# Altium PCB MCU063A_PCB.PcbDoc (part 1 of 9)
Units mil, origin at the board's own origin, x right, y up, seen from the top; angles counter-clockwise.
Board outline 4165.01 x 2371.03 mil, 10 copper layers (Top Layer, Internal Plane 2, Signal Layer 3, Signal Layer 4, Internal Plane 5, Internal Plane 6, Signal Layer 7, Signal Layer 8, Internal Plane 9, Bottom), stack 59.9 mil thick; 436 components, 392 nets, 1750 pads, 1250 vias.
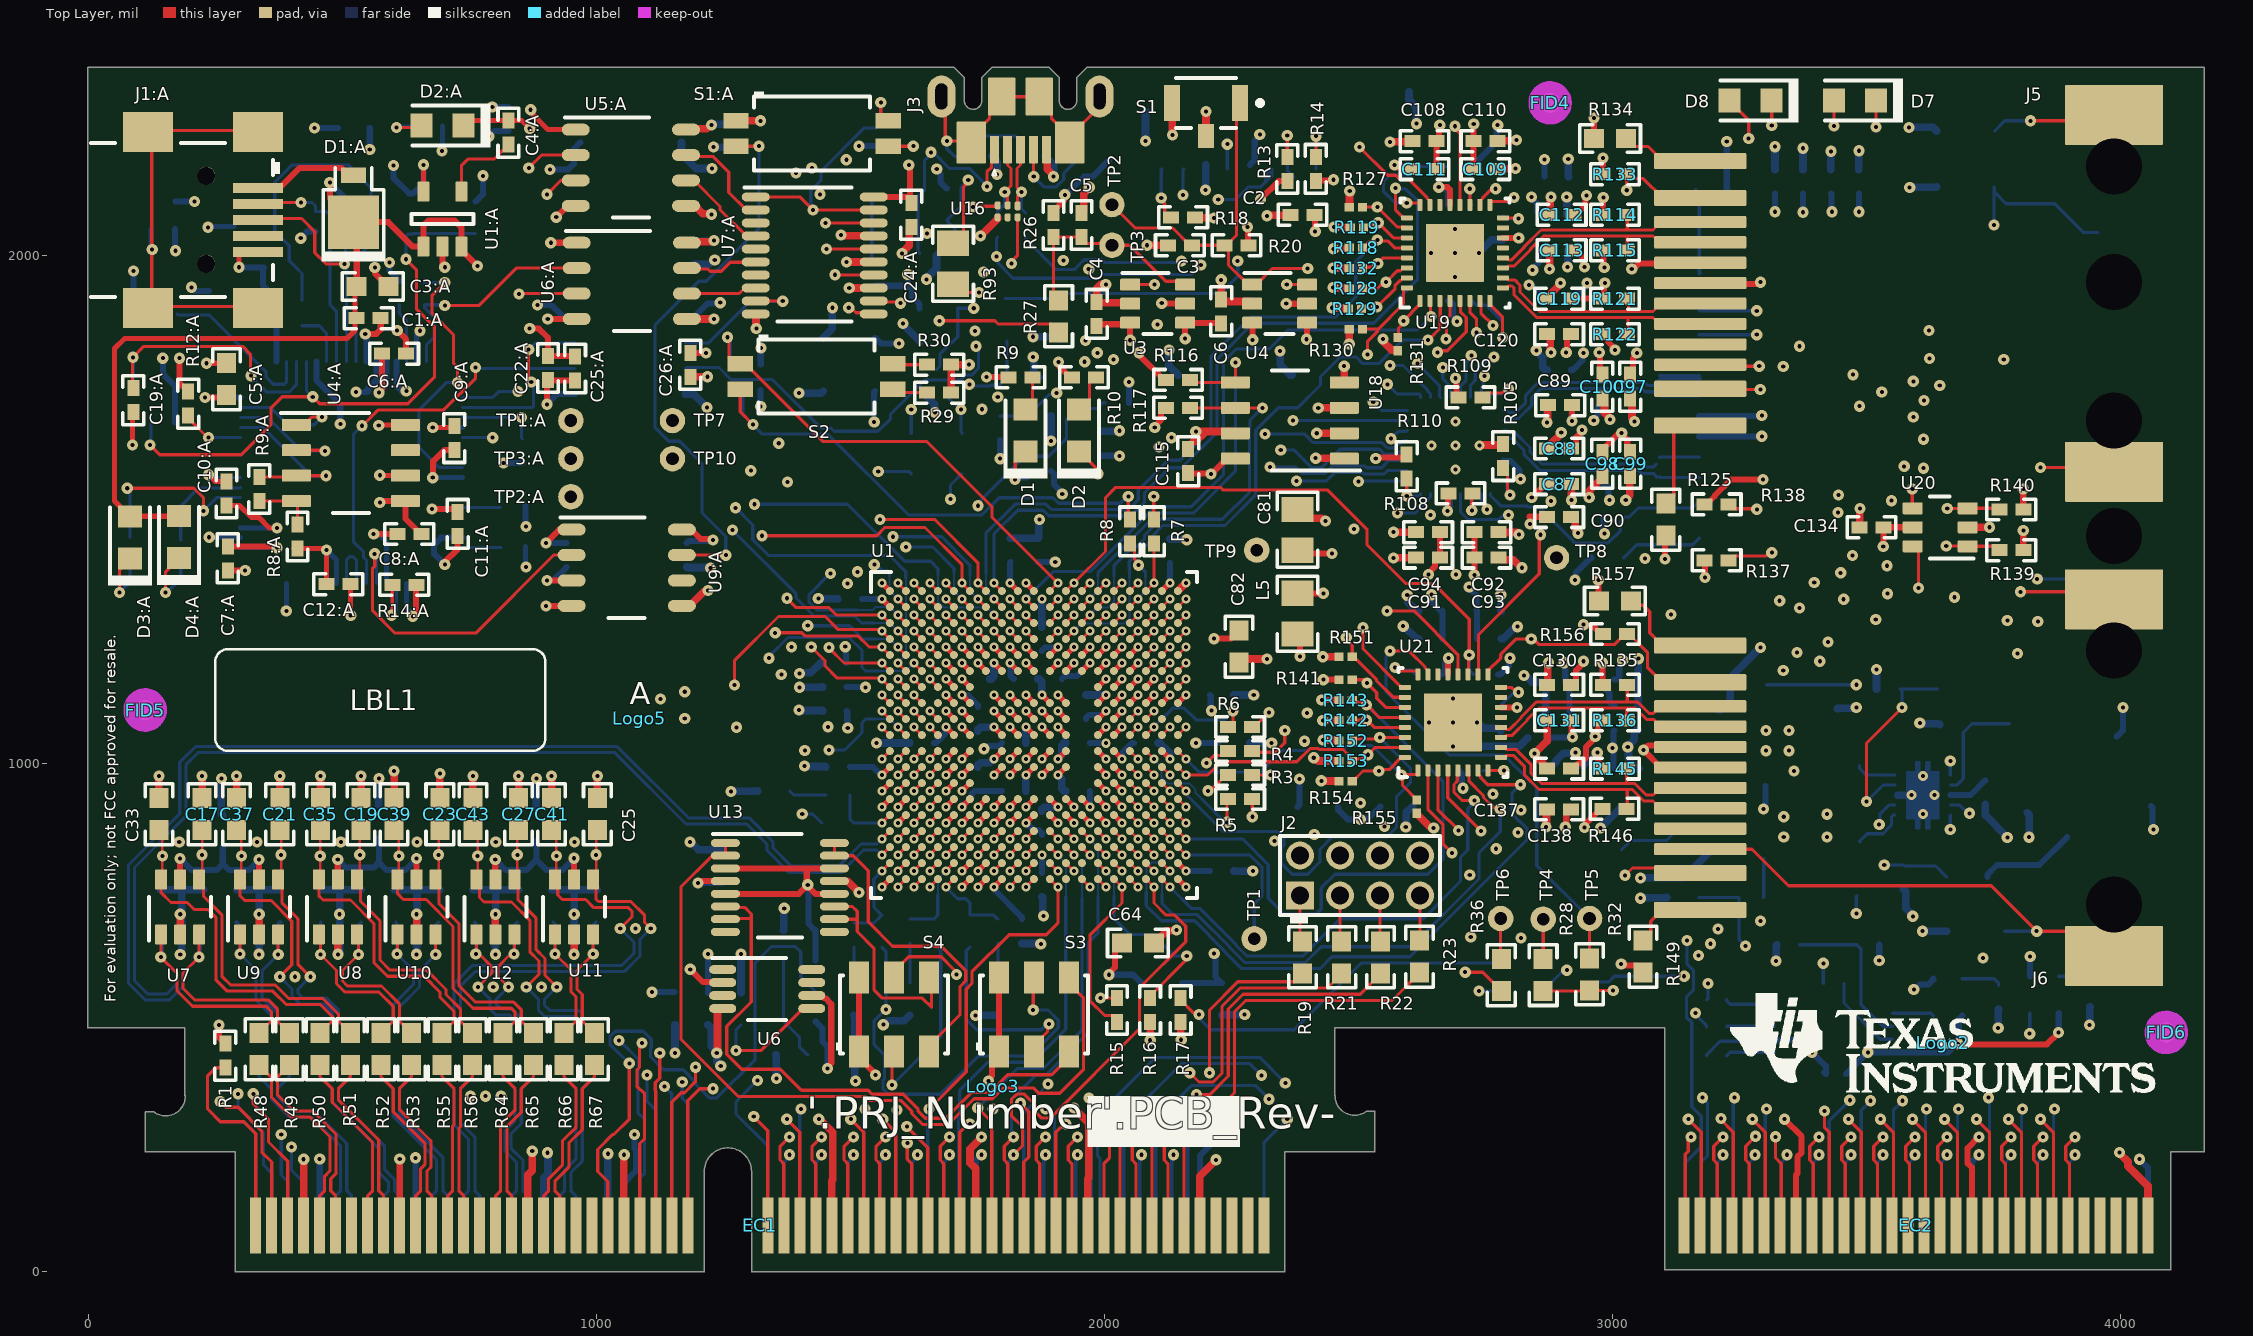
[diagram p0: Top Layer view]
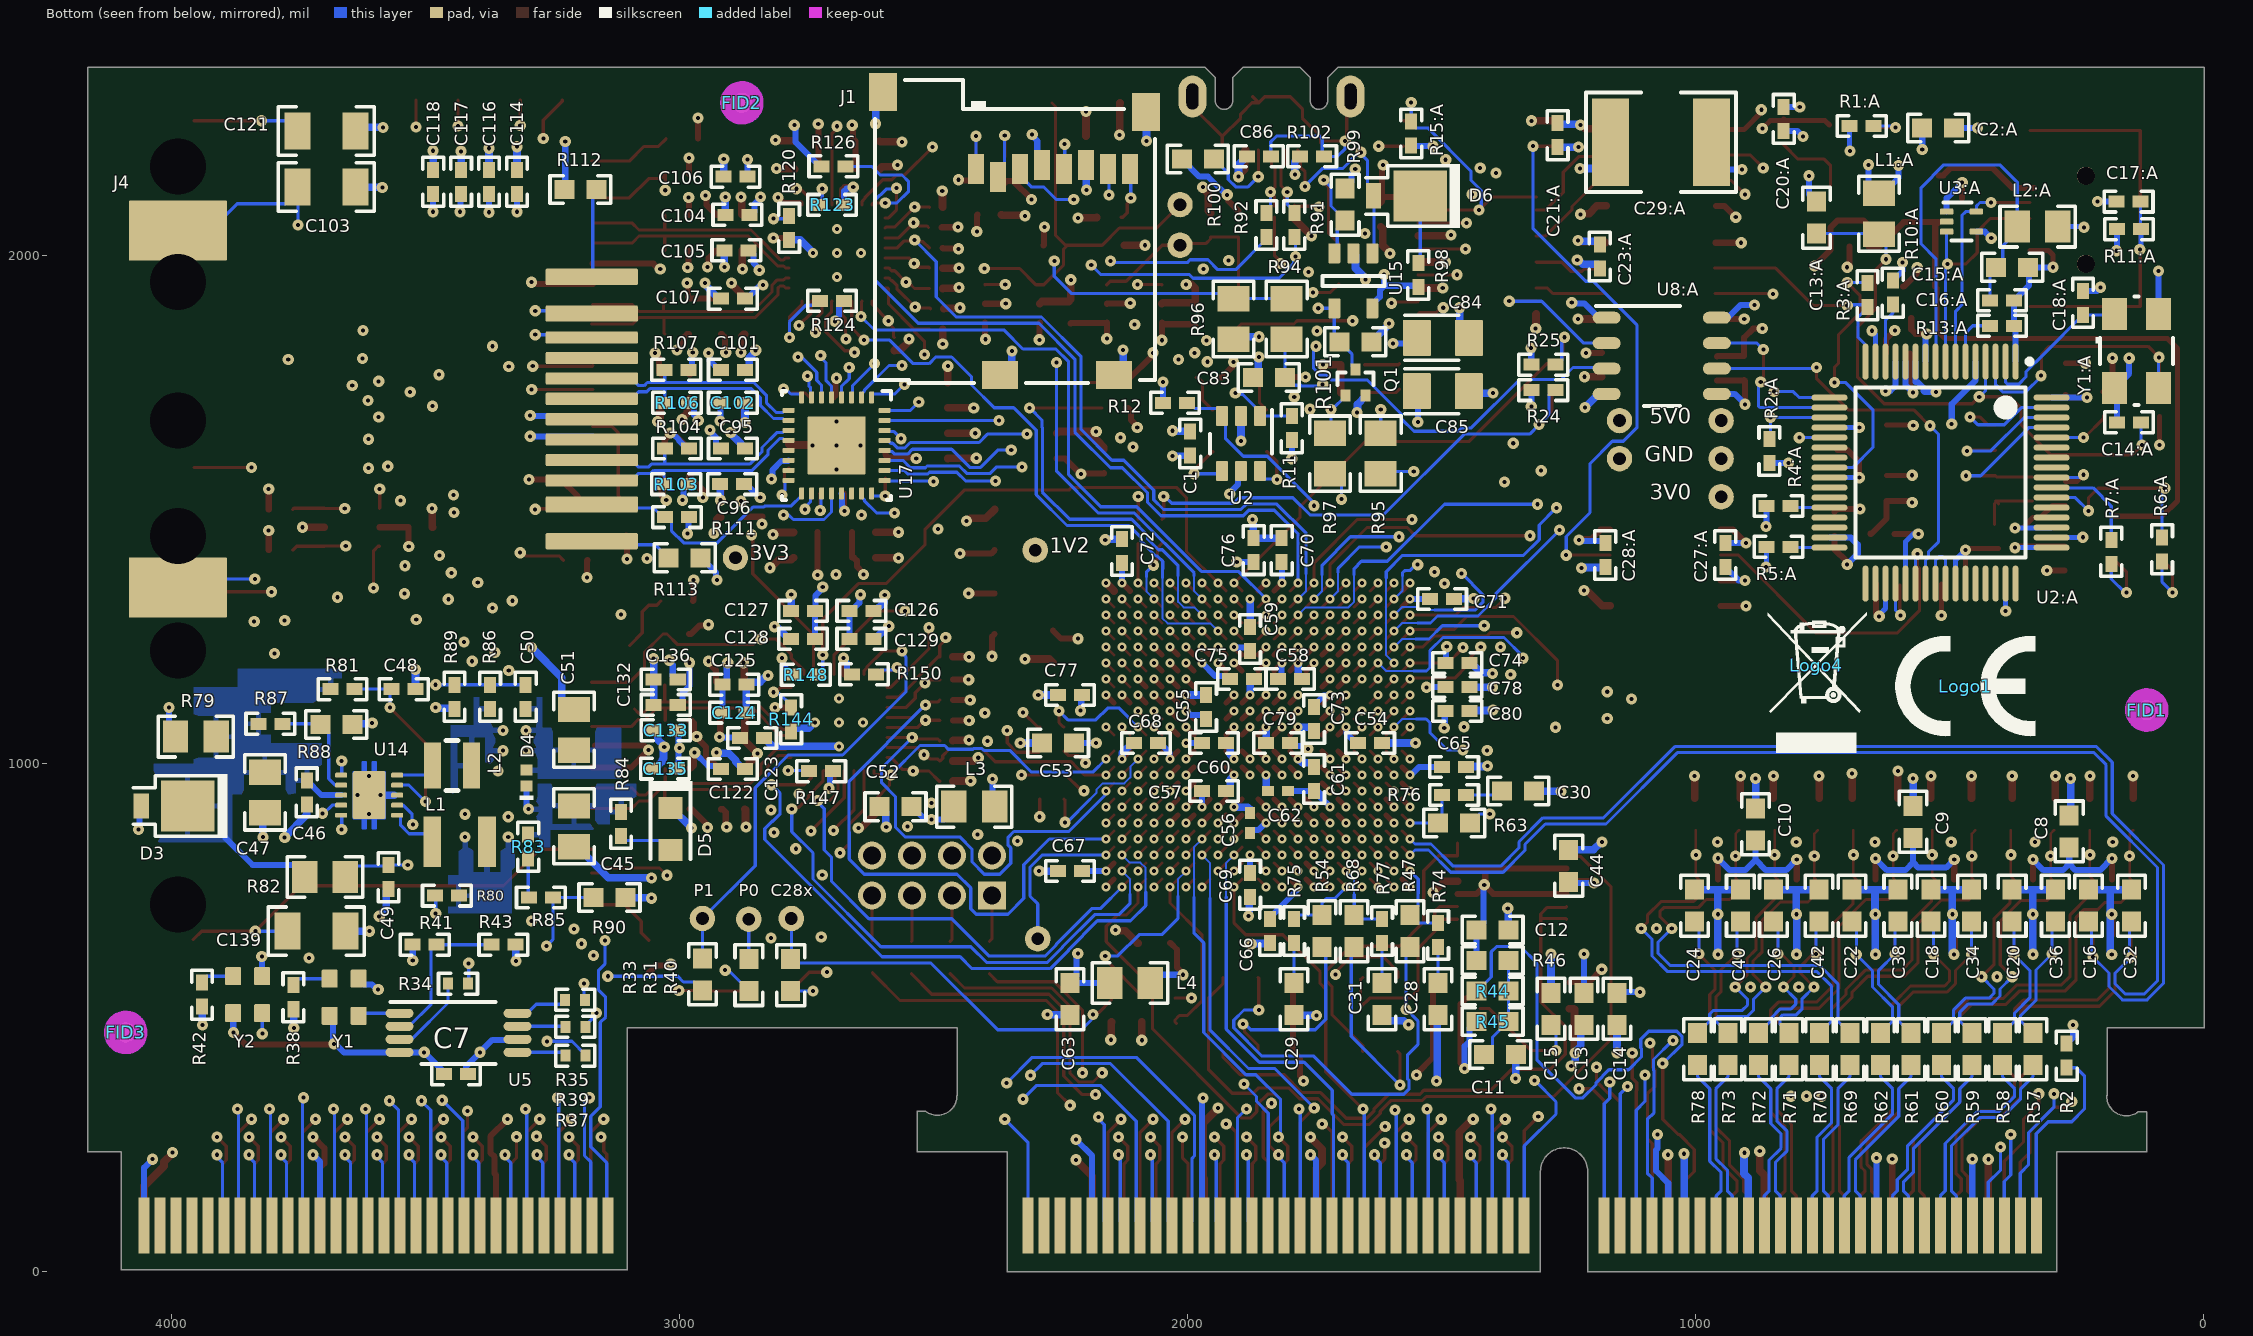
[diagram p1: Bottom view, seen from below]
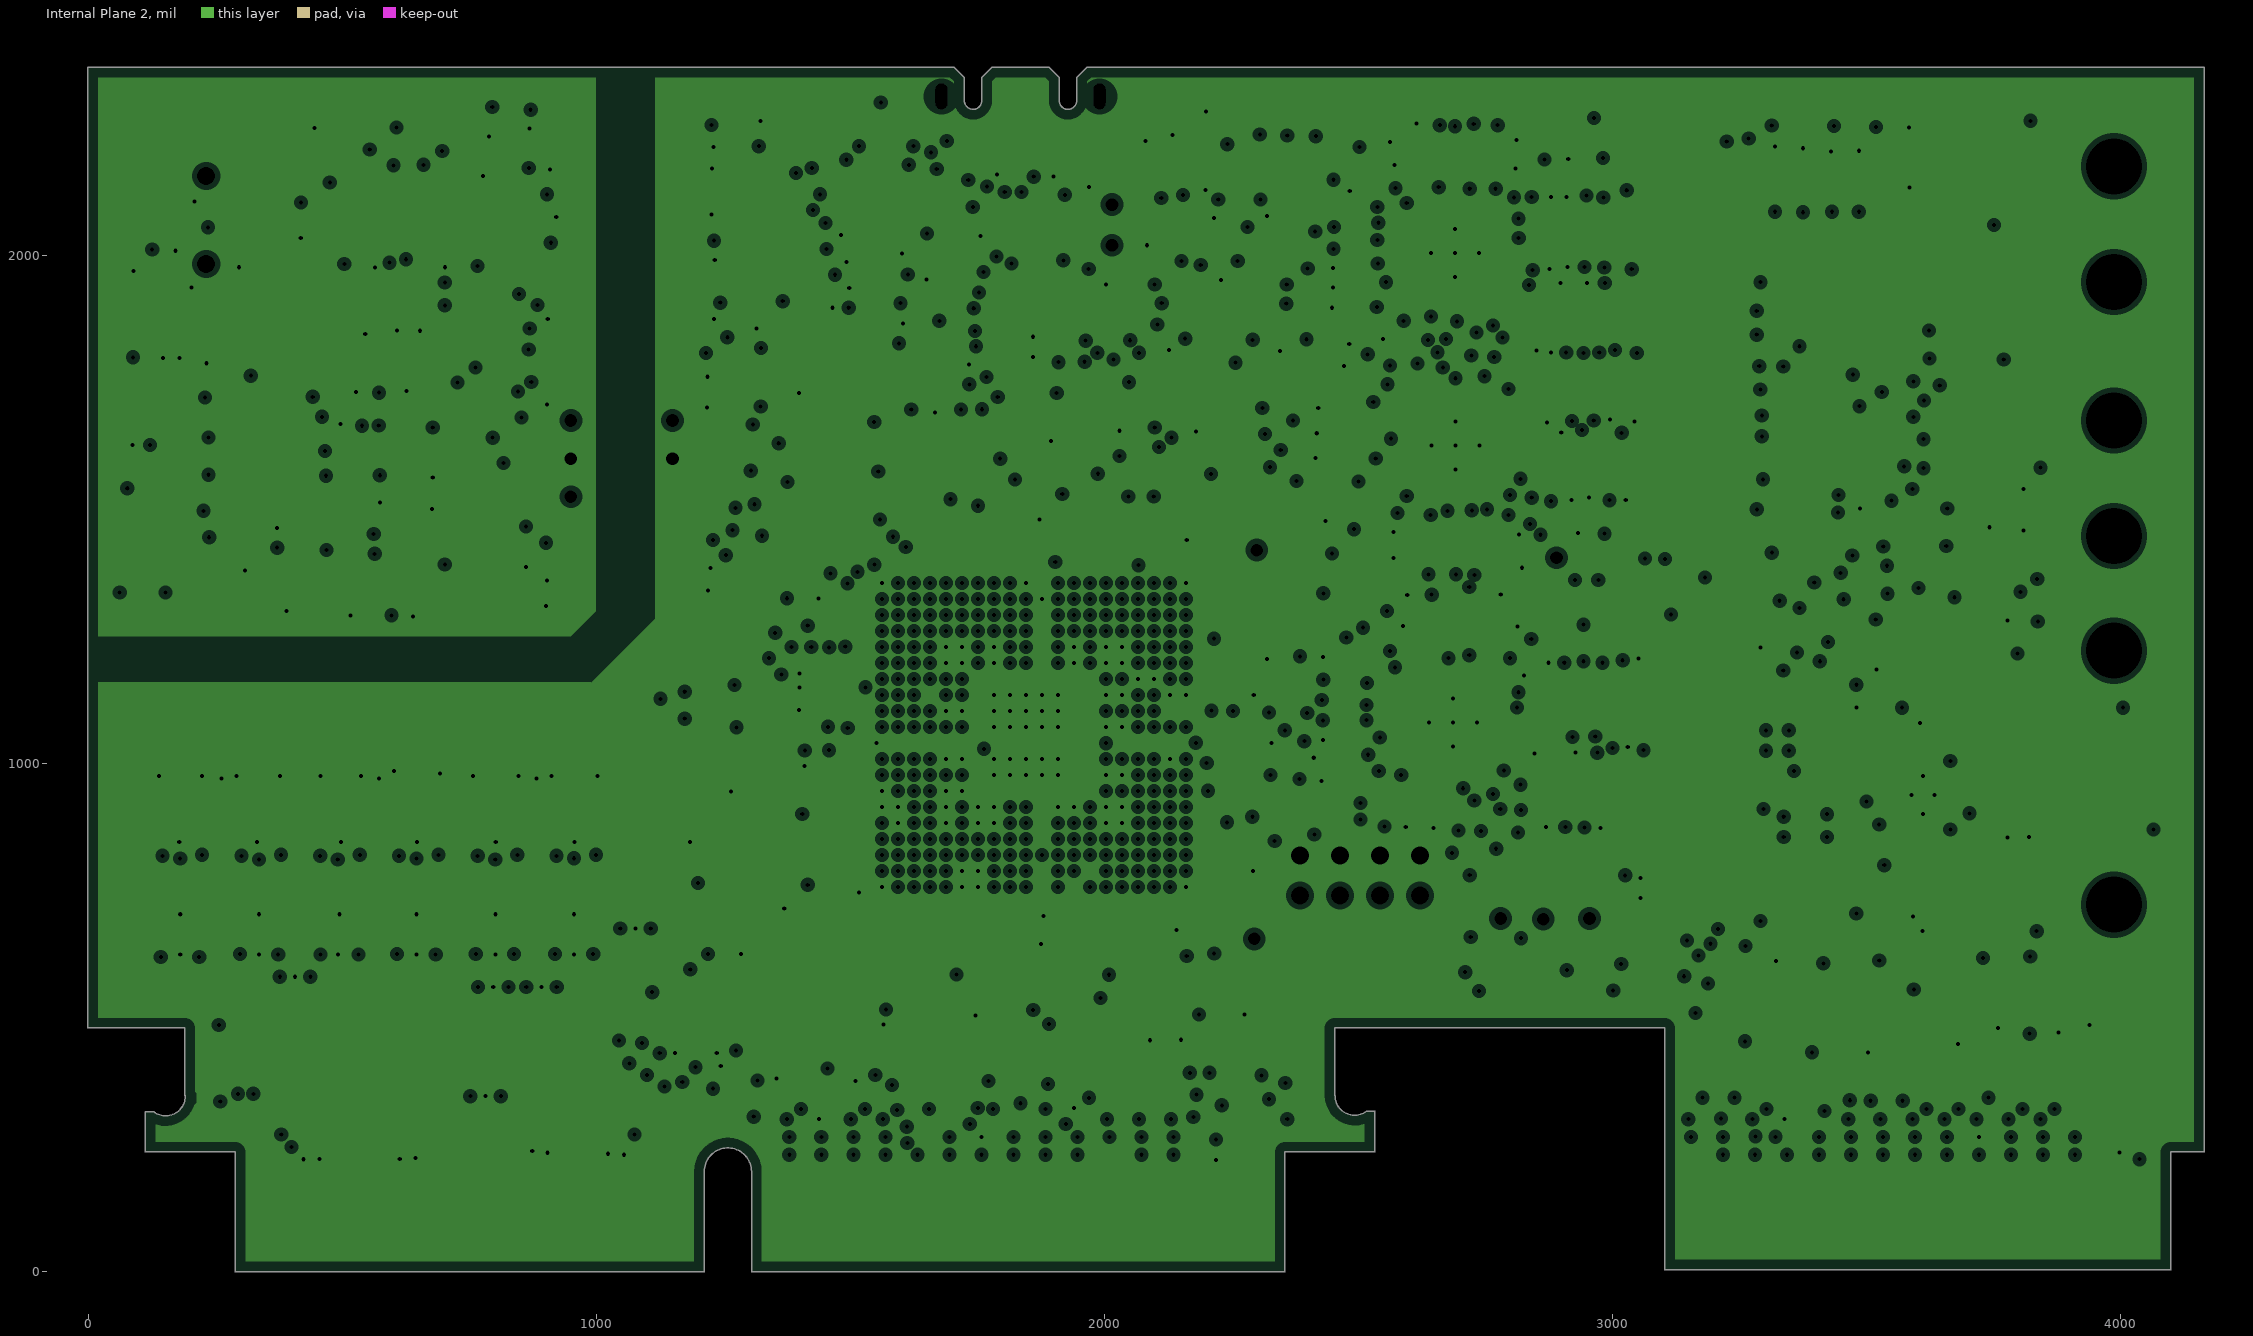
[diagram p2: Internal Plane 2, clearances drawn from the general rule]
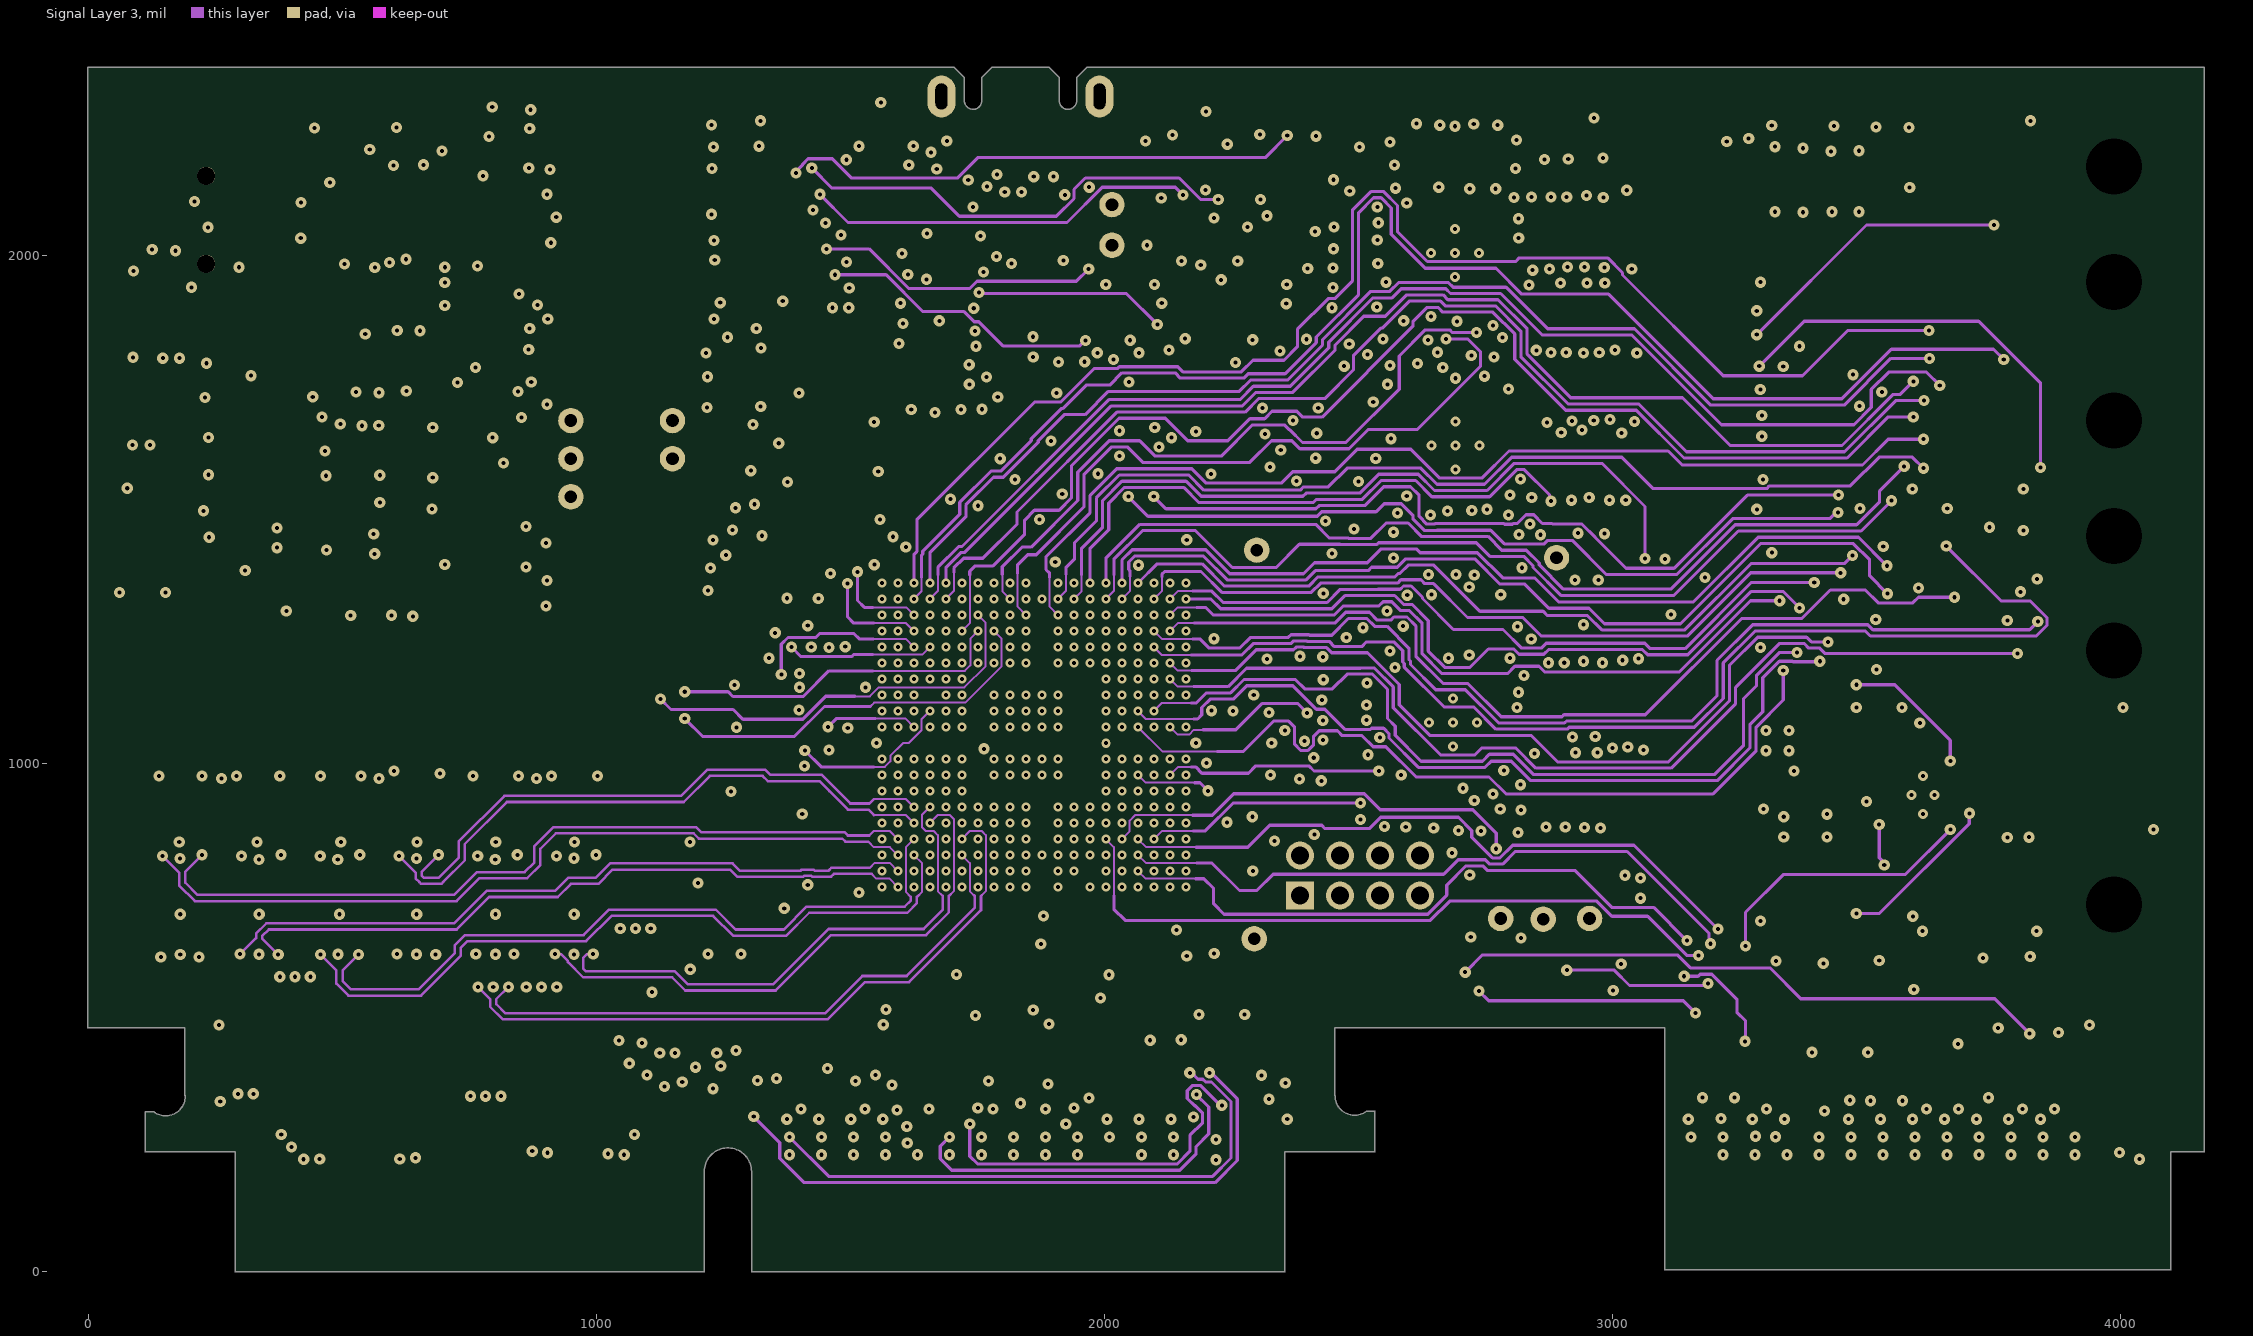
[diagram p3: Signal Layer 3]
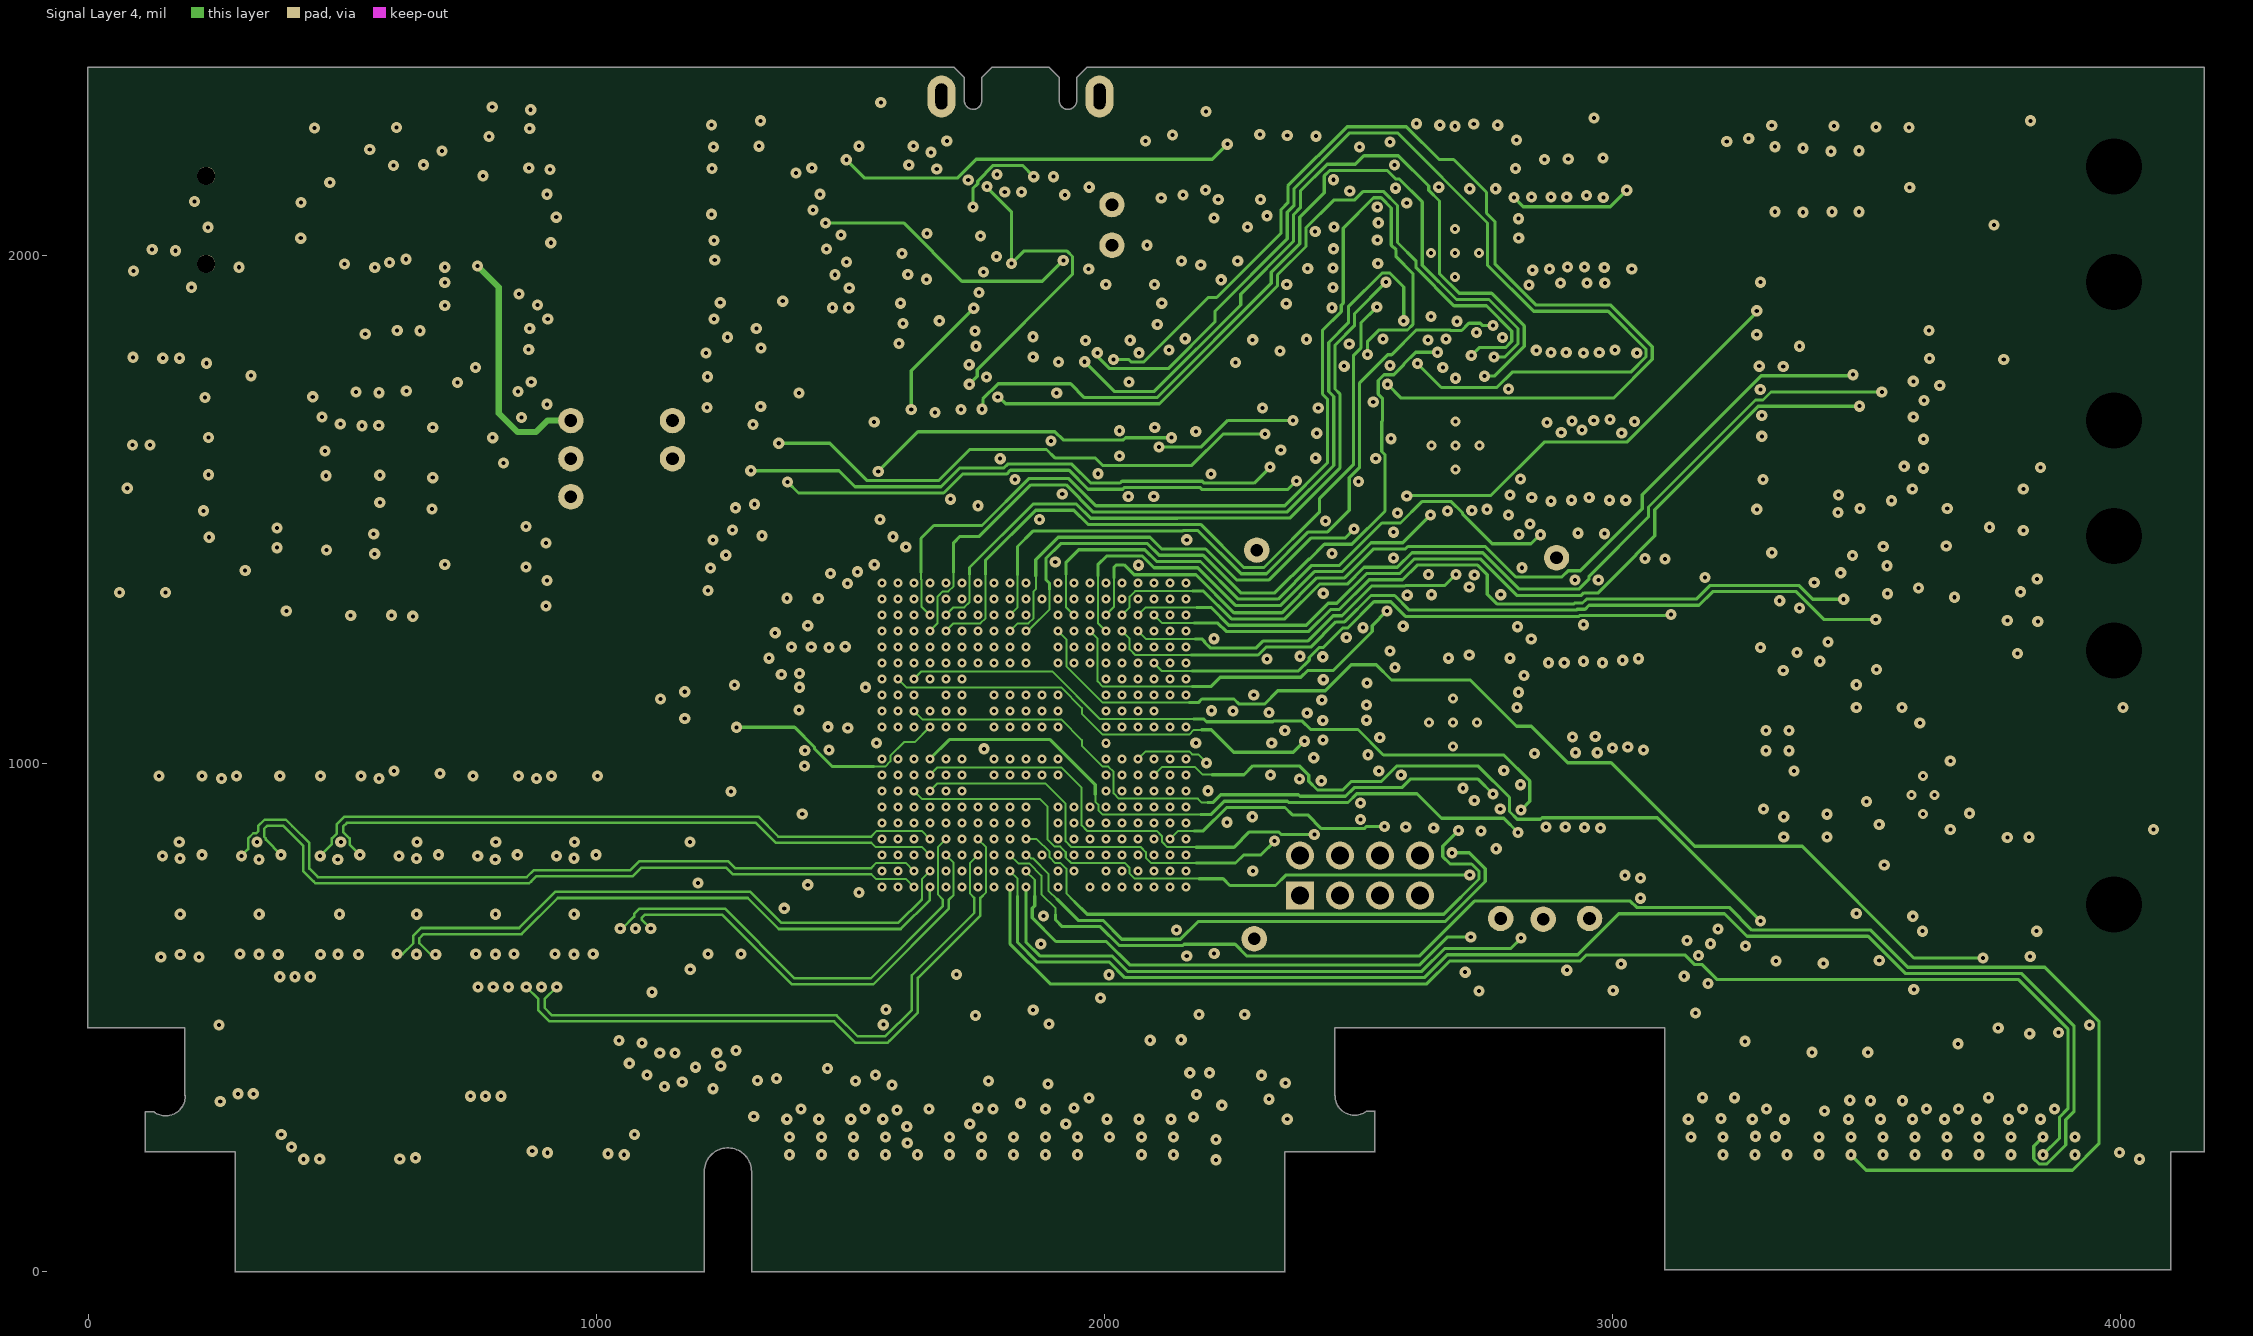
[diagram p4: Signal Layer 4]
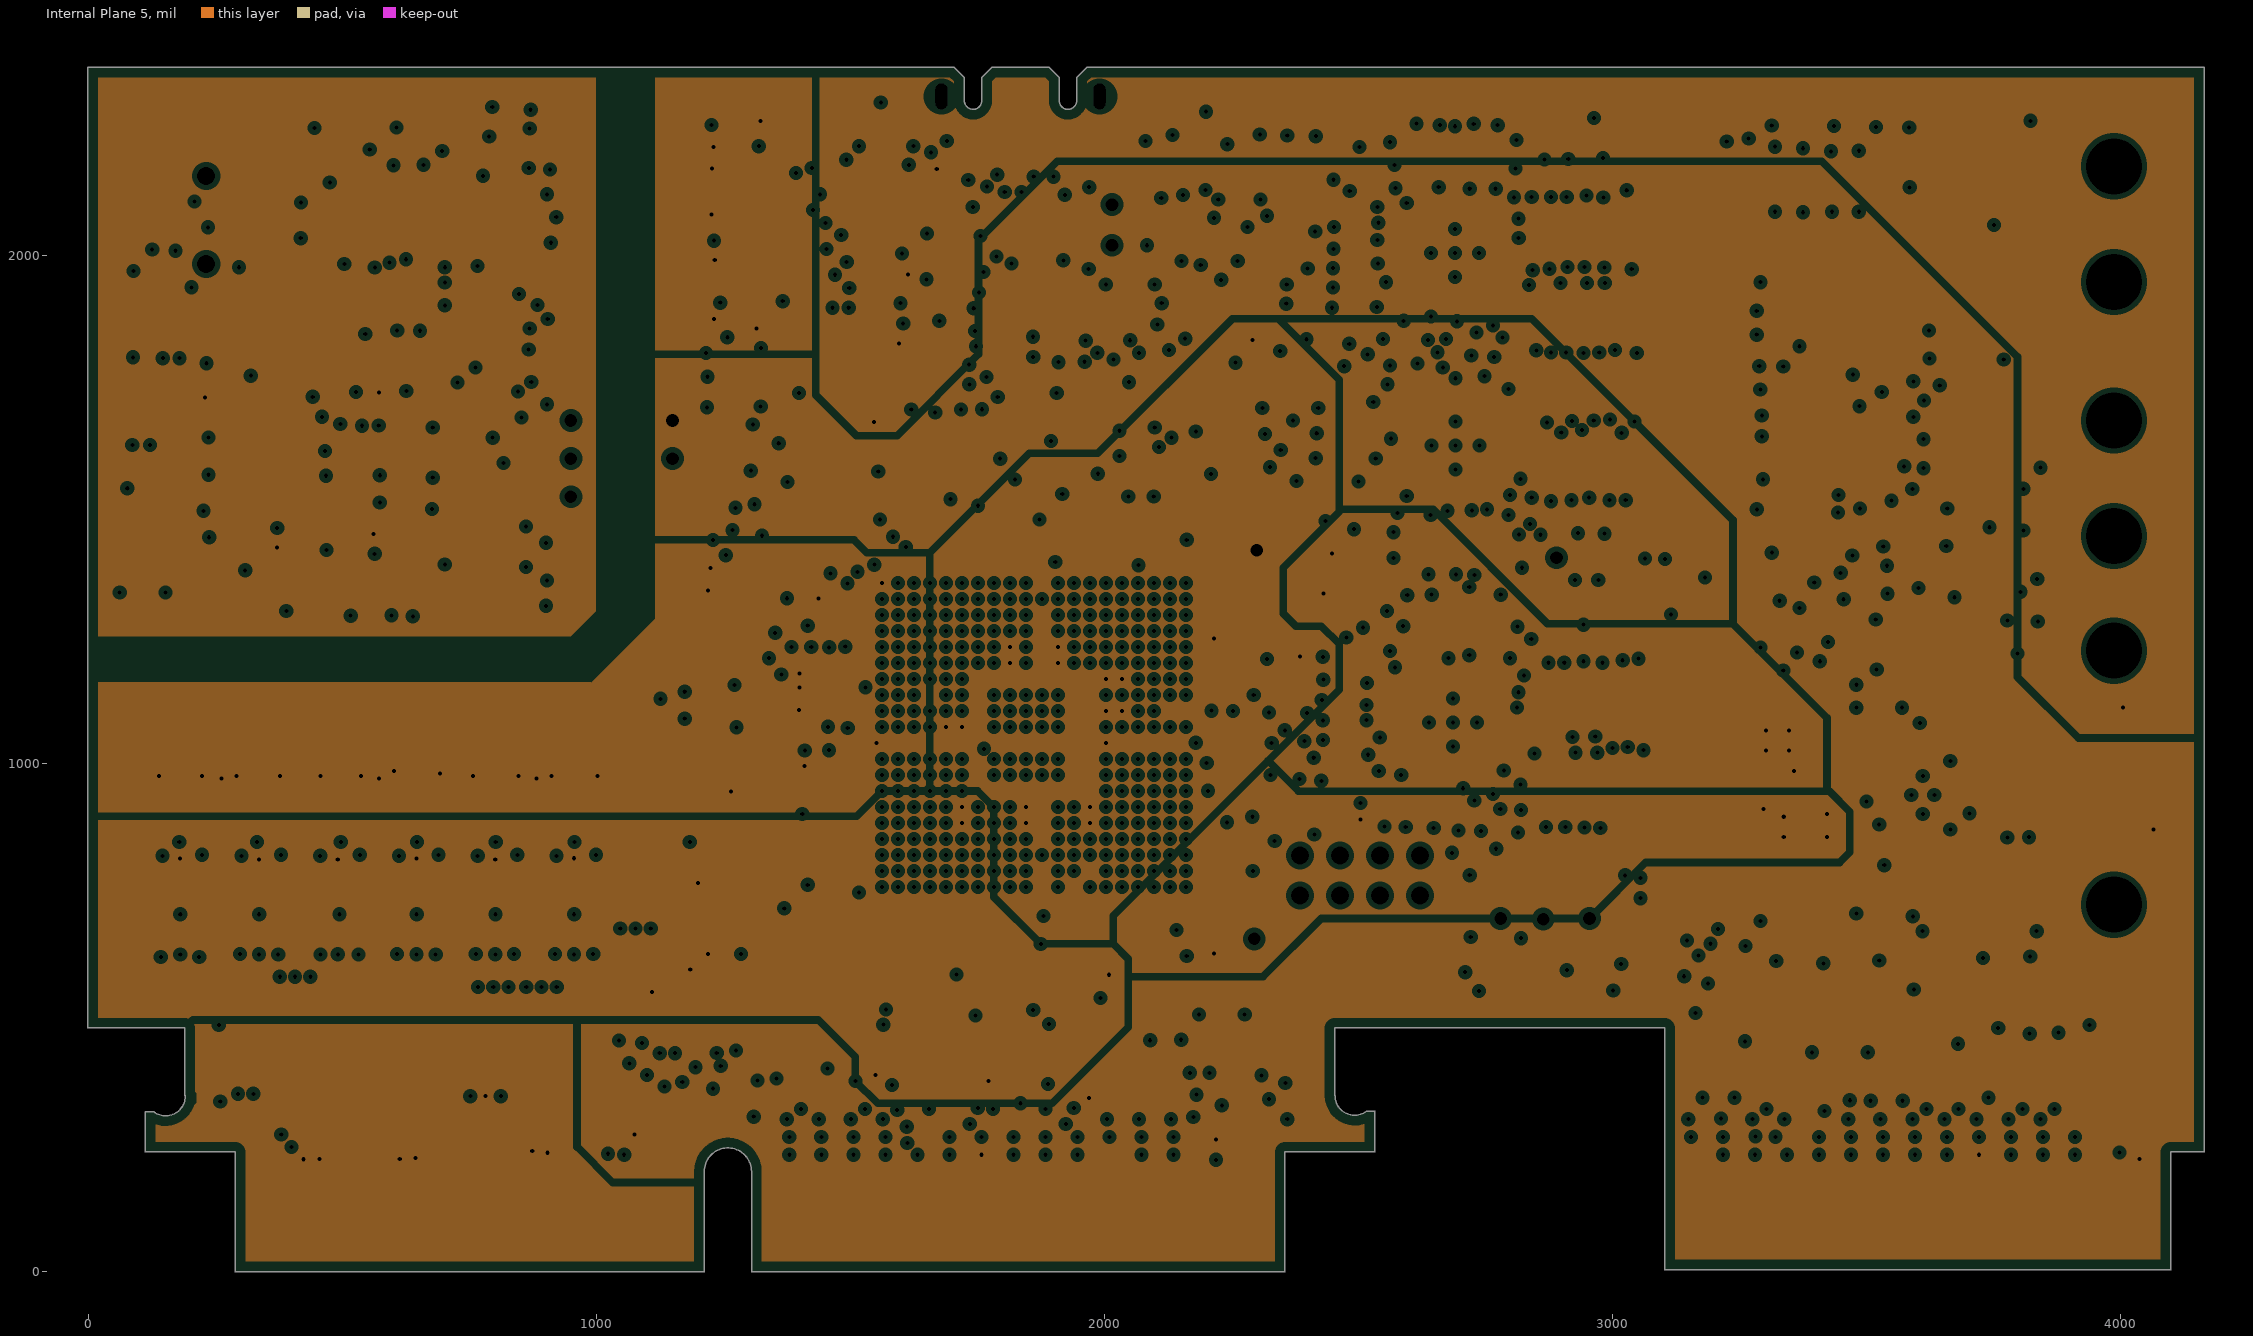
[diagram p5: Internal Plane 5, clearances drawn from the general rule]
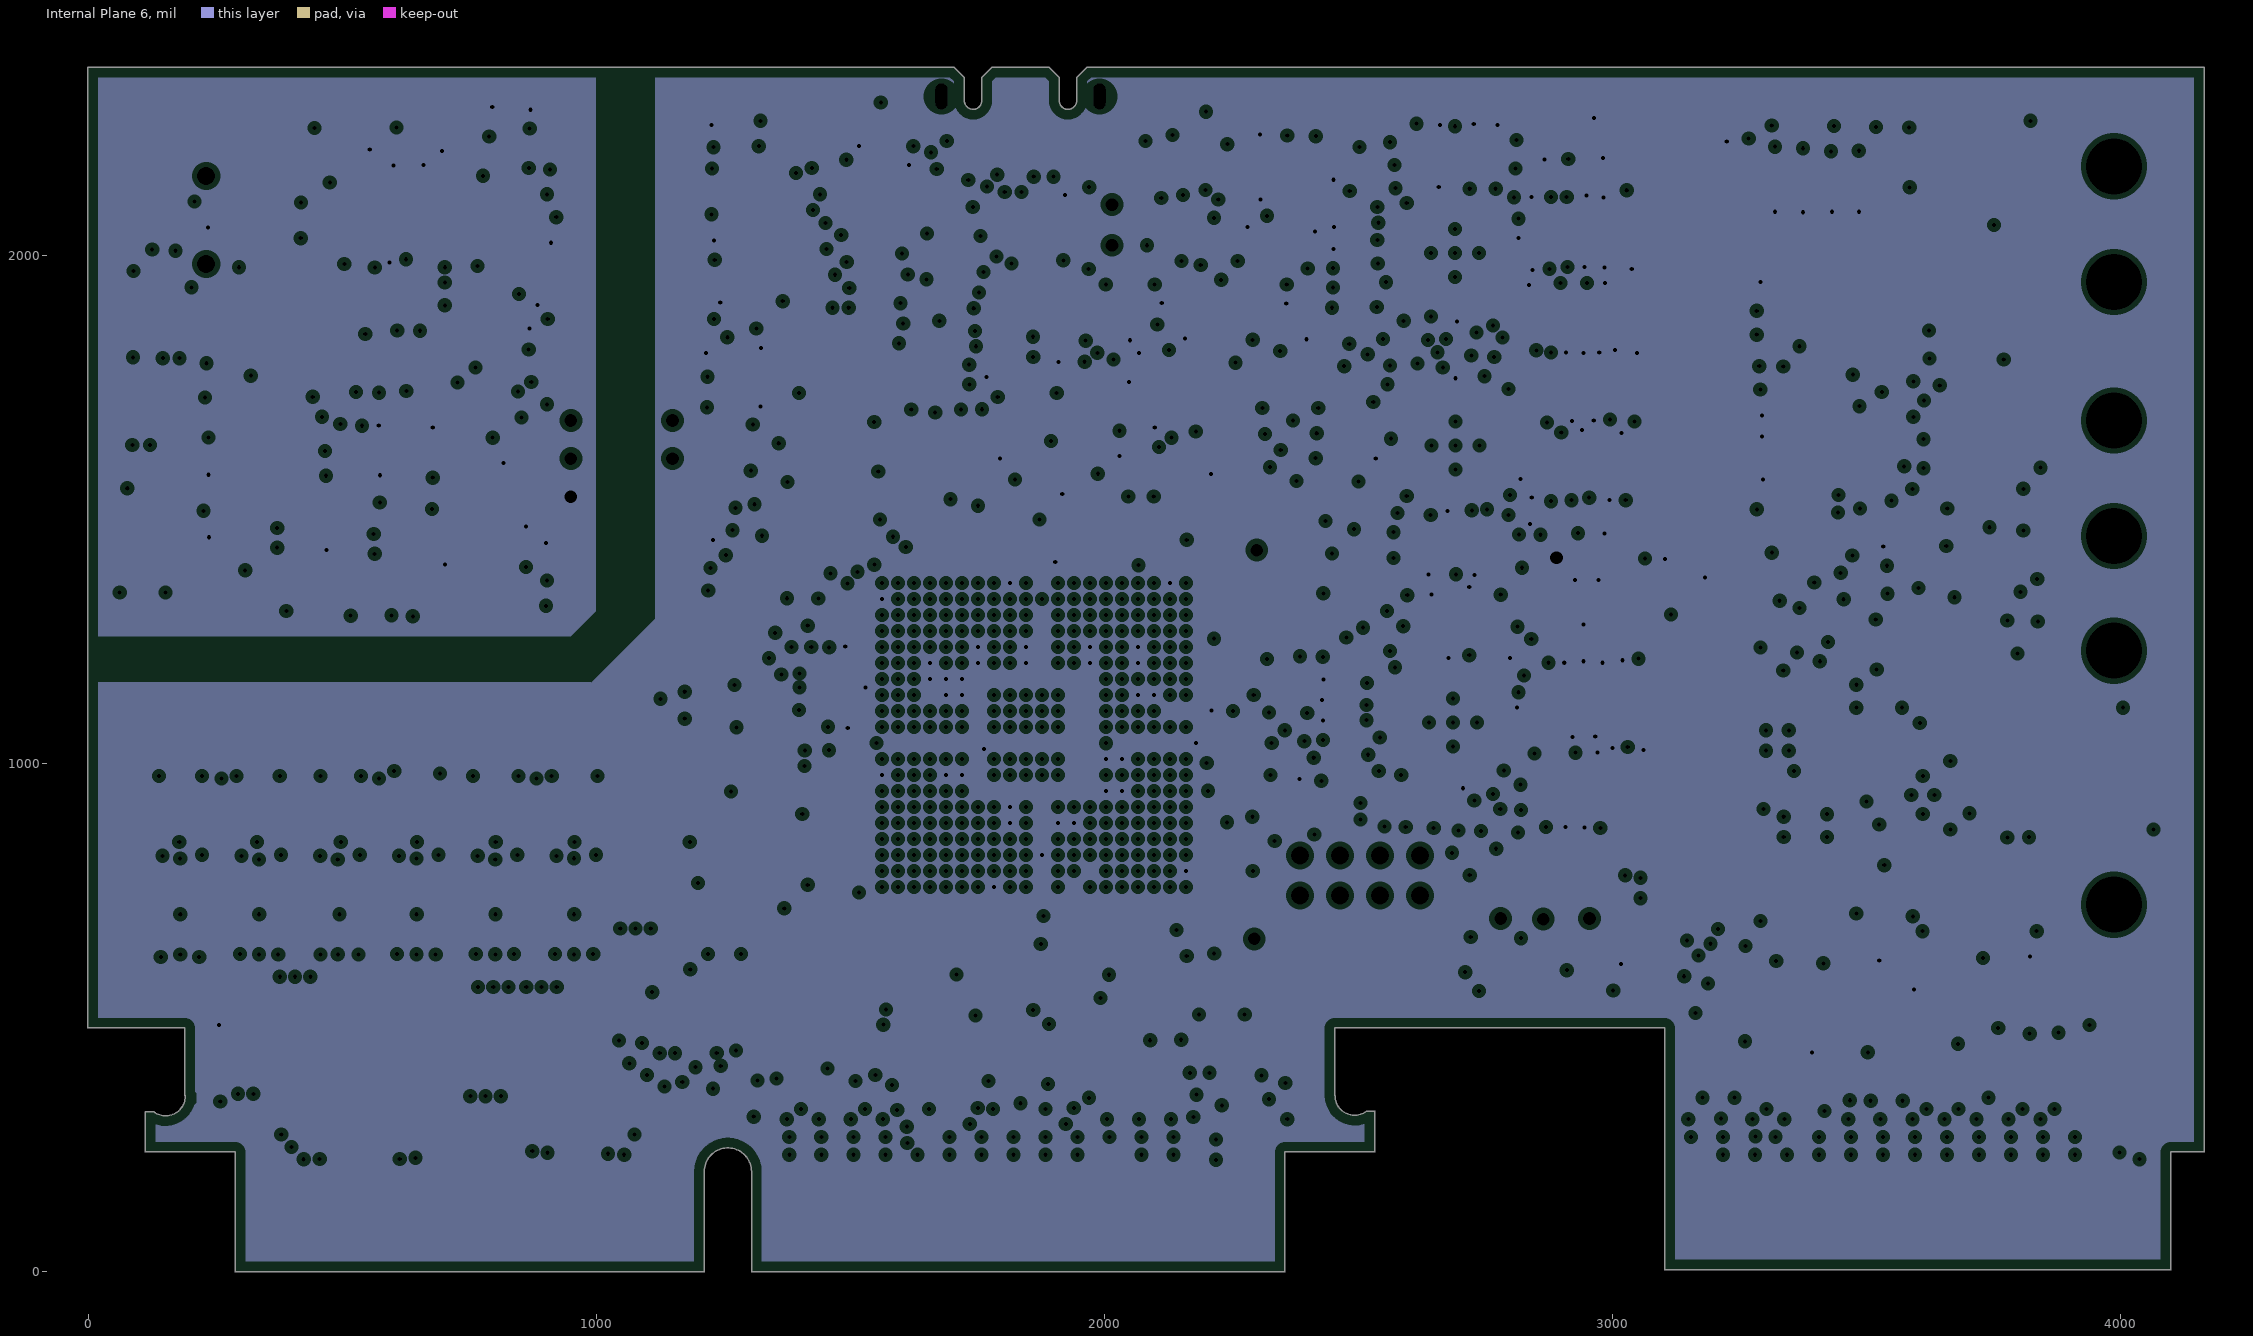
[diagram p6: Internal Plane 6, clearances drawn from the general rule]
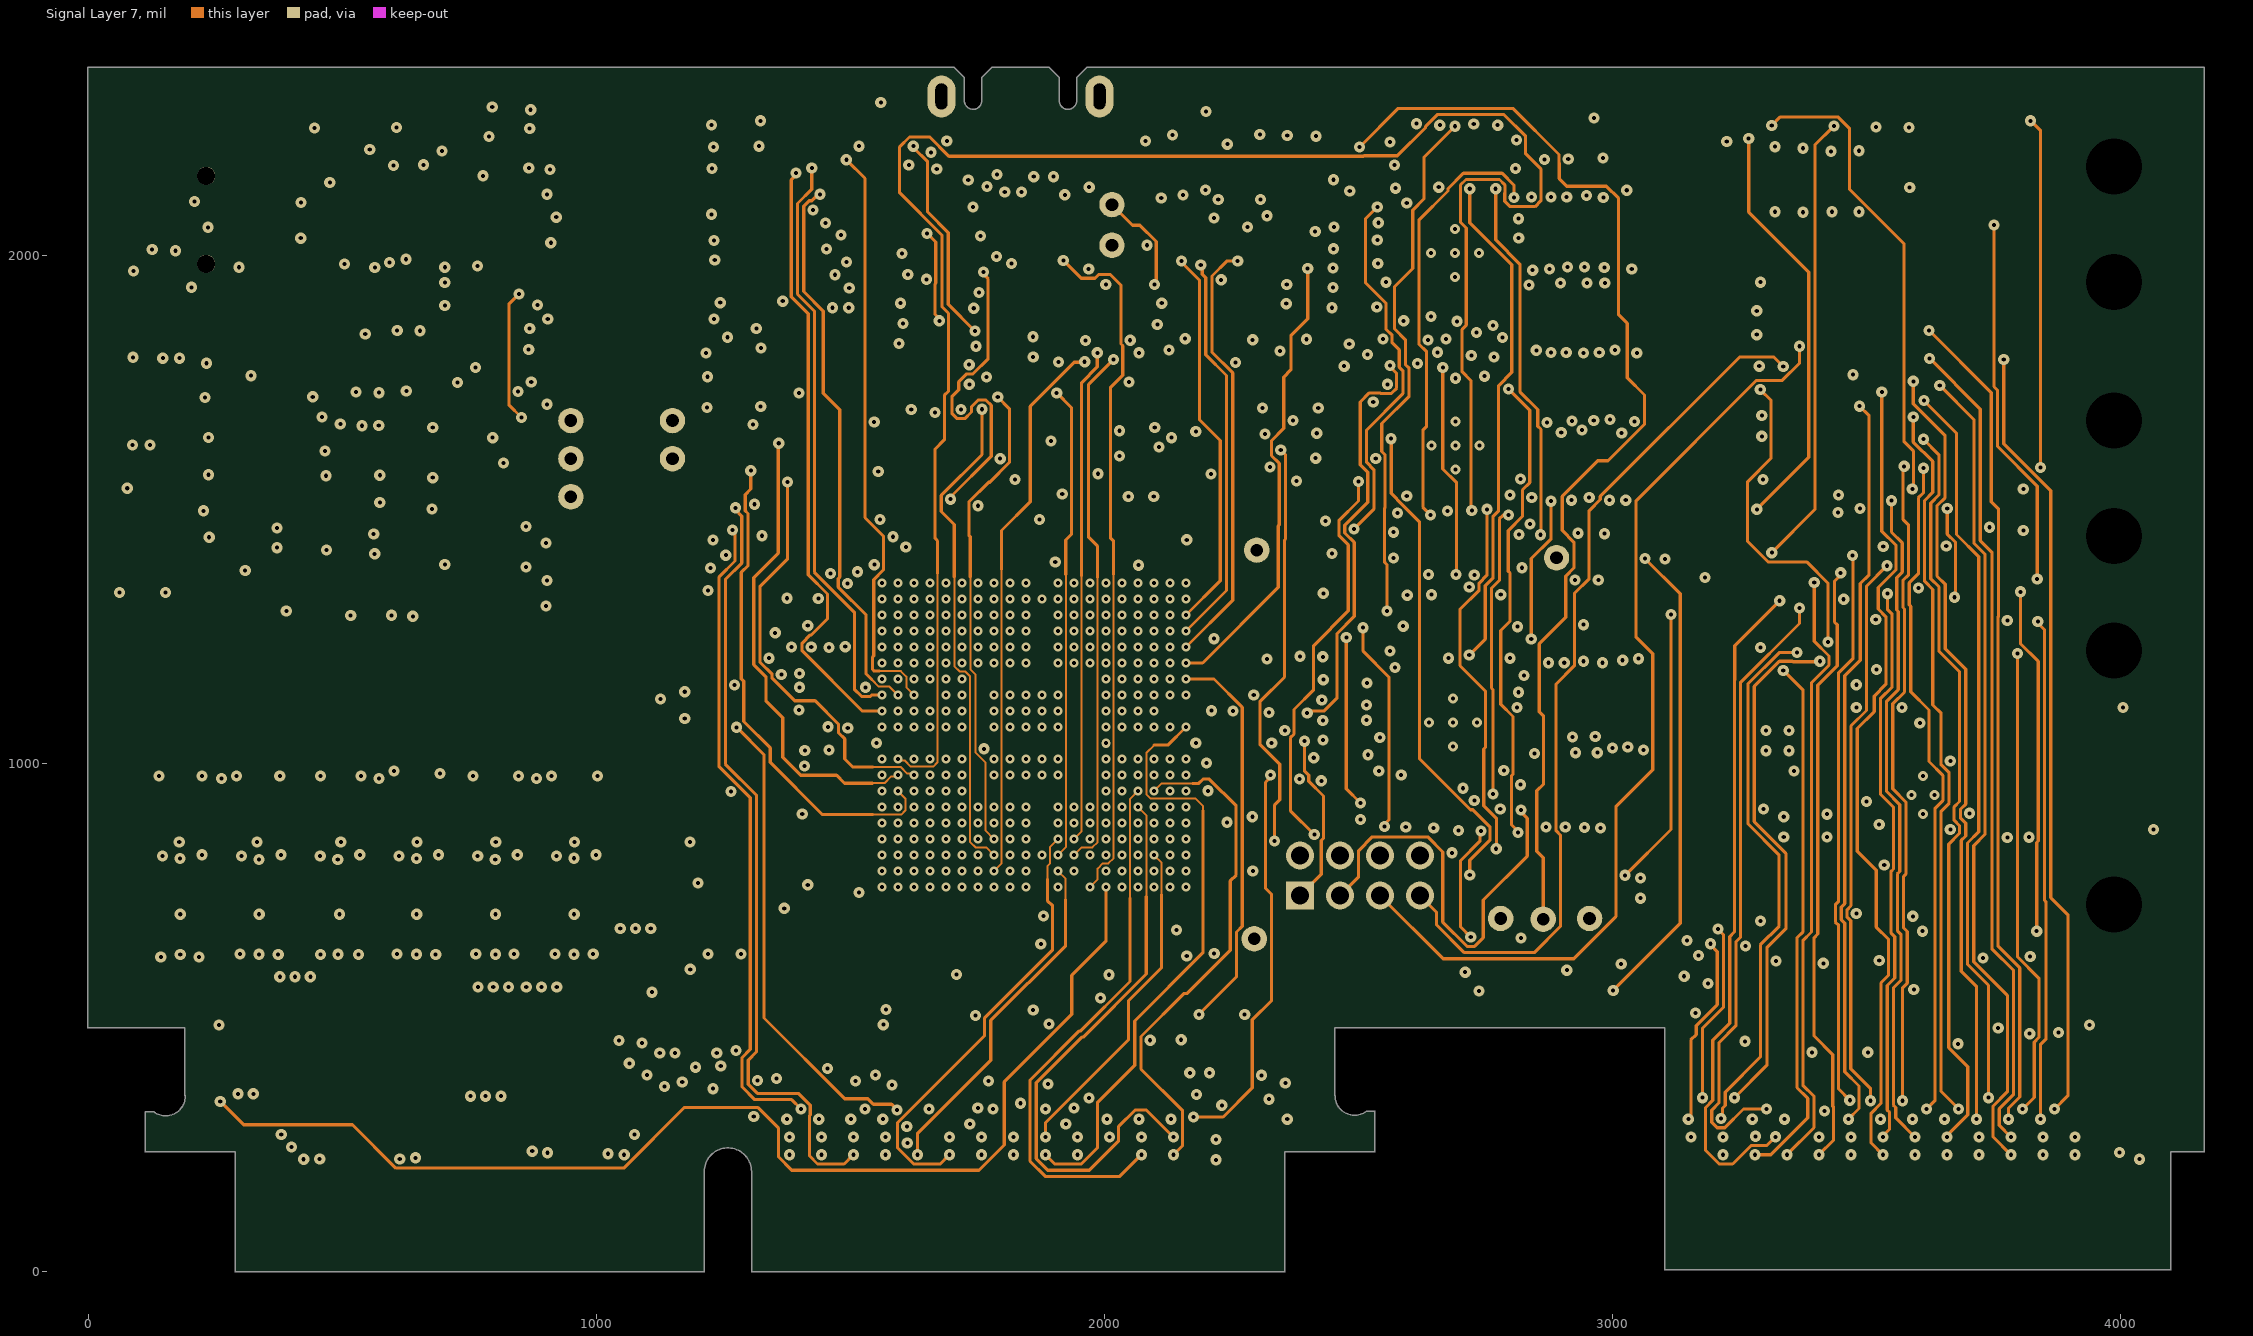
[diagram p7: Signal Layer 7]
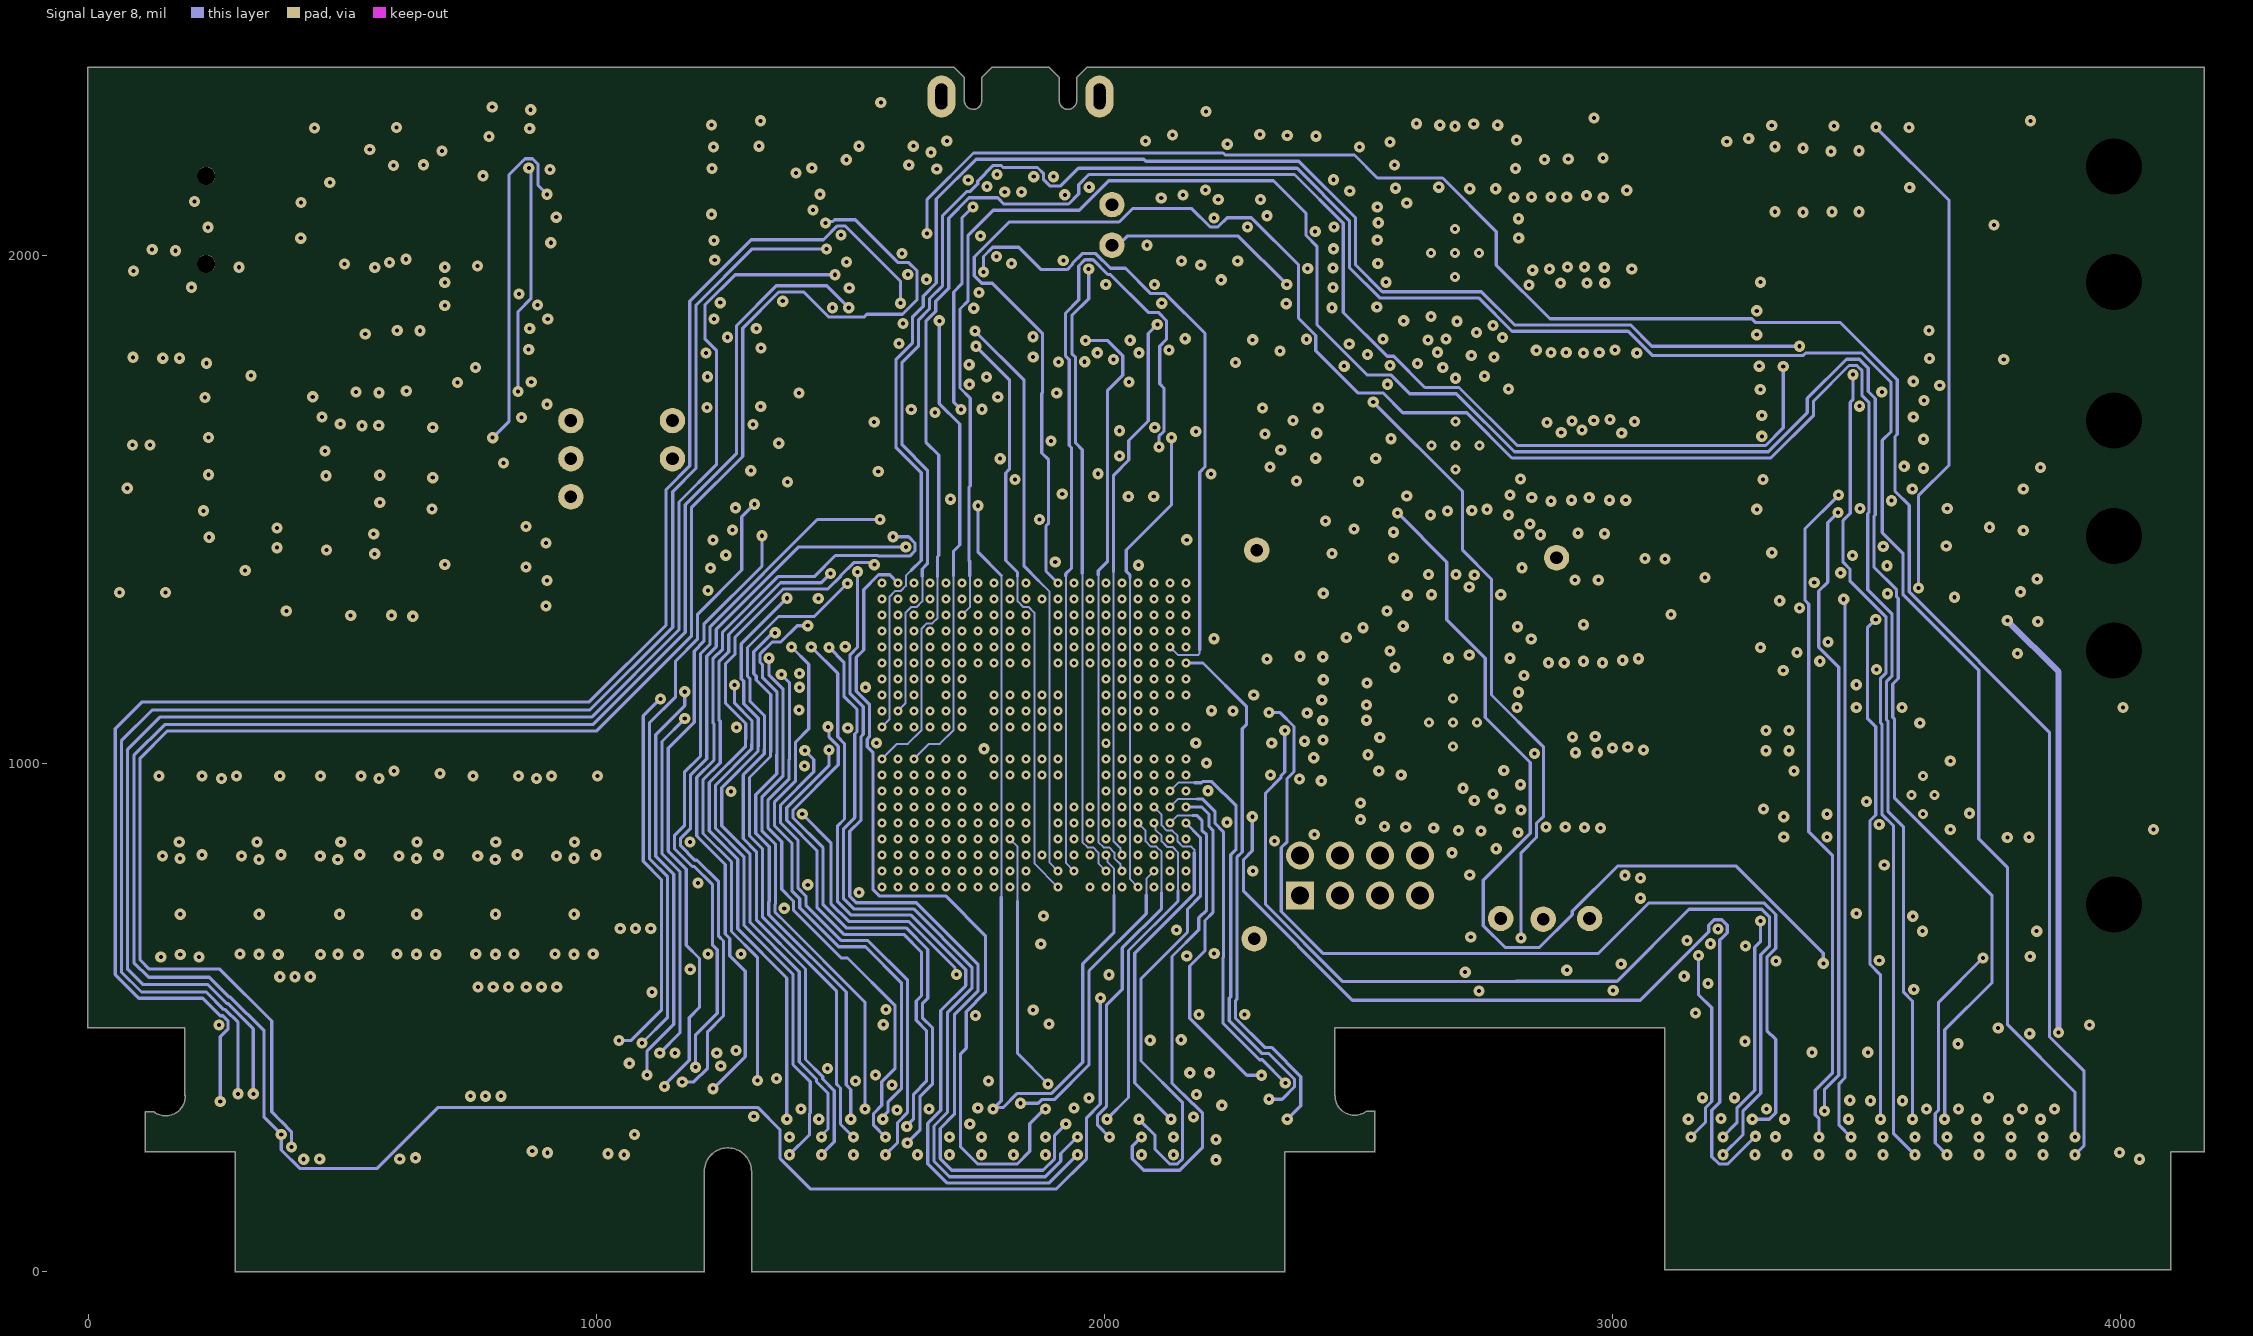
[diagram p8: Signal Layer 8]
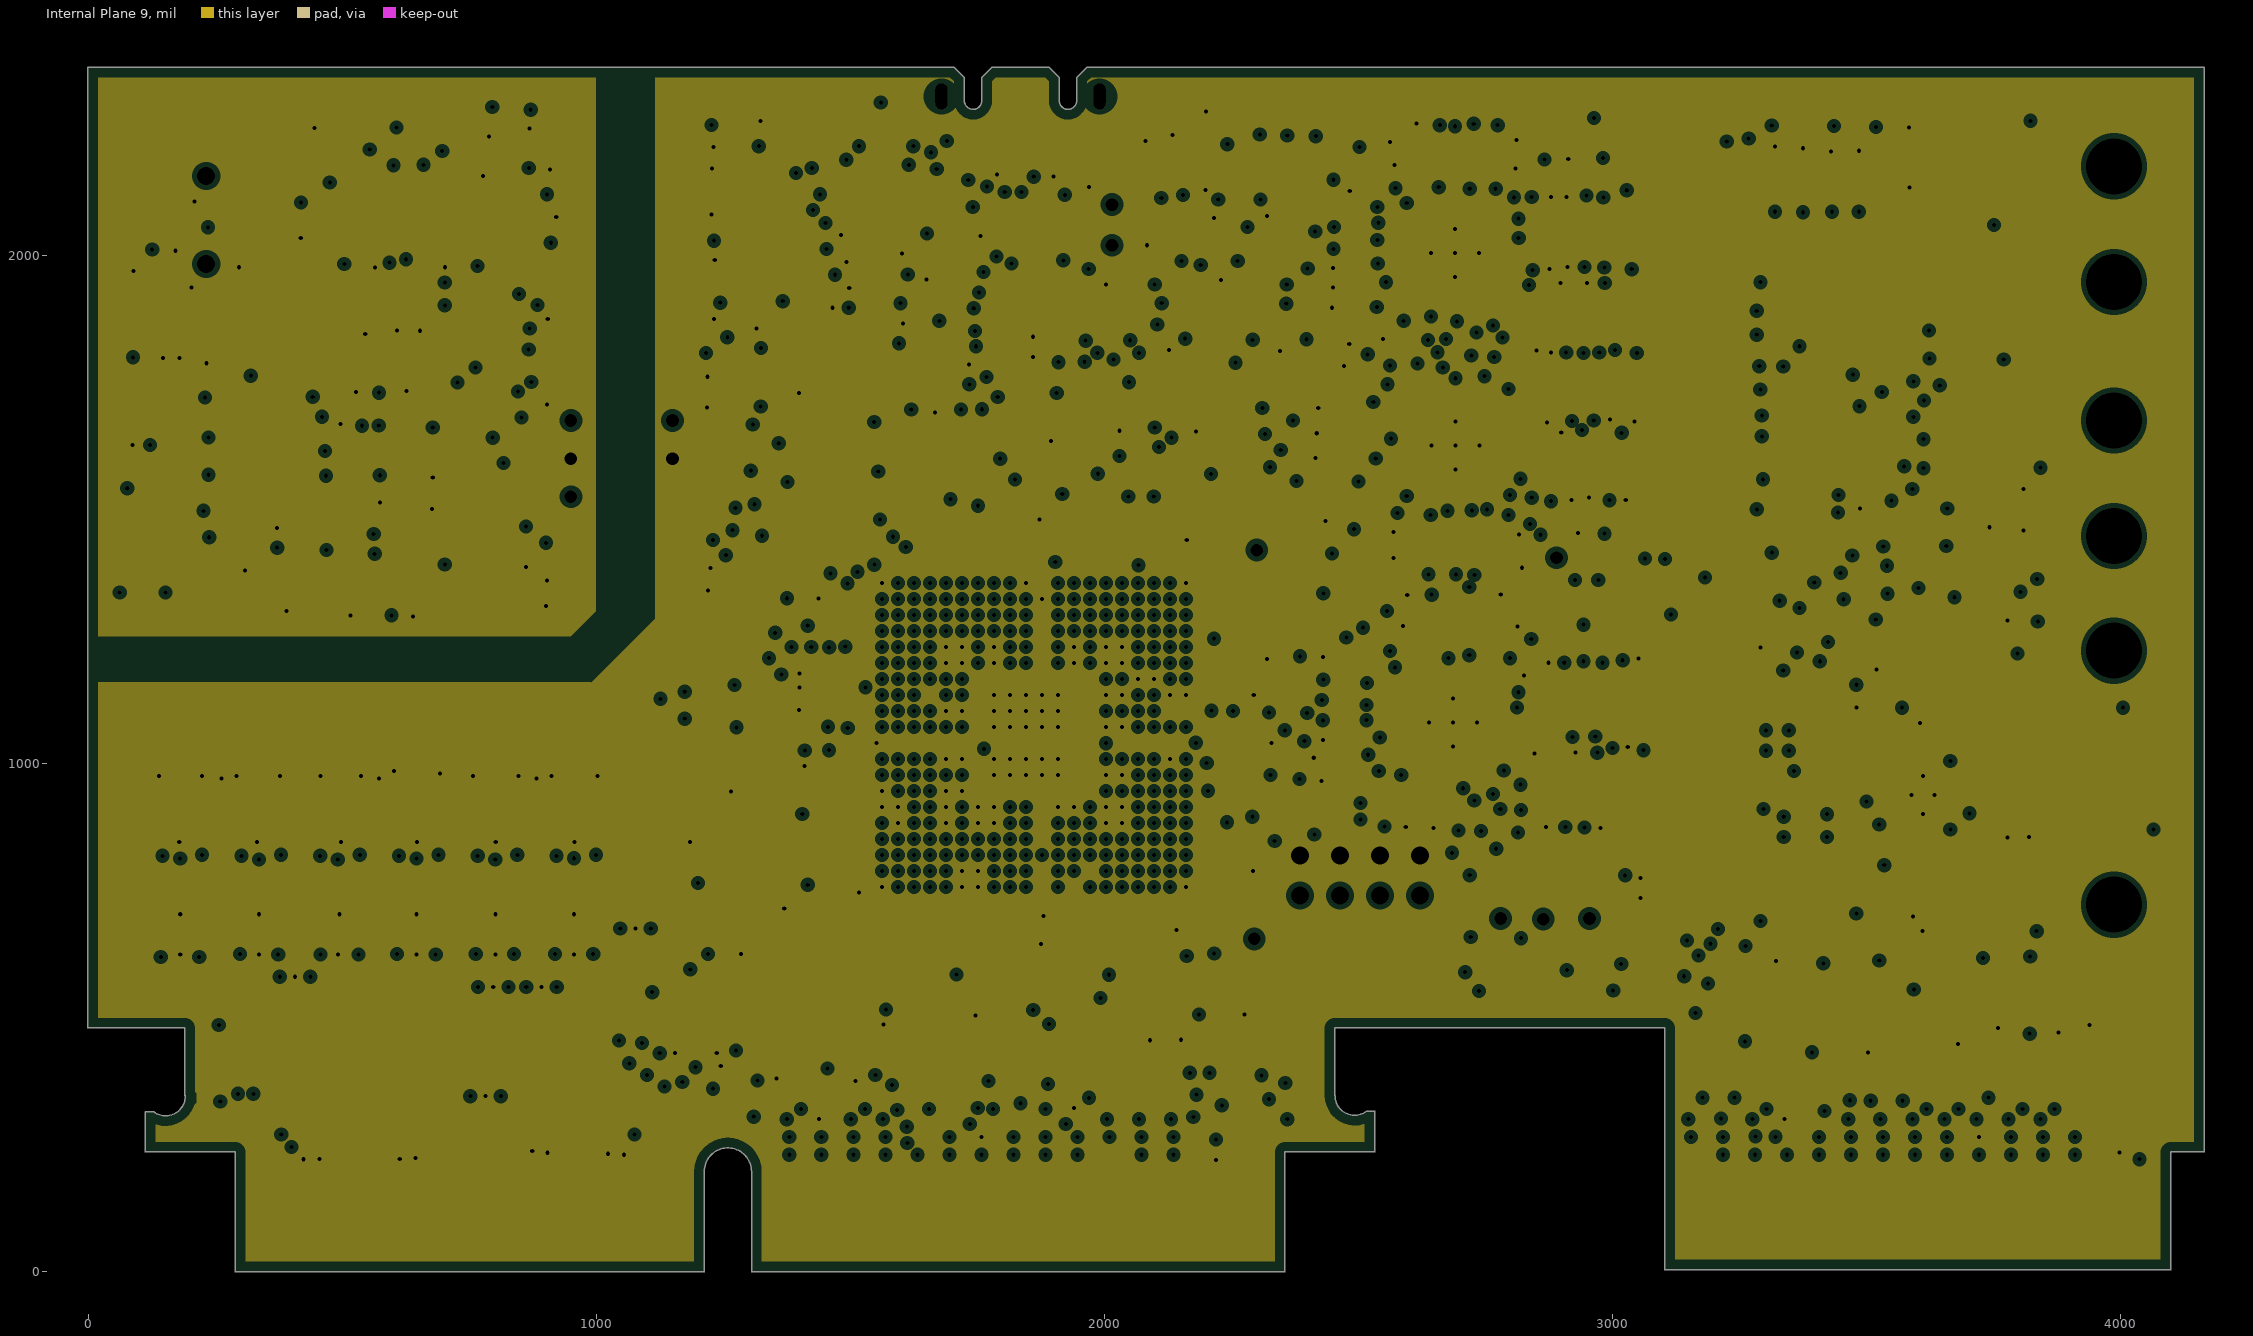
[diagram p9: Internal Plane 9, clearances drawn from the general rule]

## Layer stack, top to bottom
Top Solder: solder mask 0.8, Solder Resist, Dk 3.6
Top Layer: signal copper 1.45
Dielectric 1: prepreg 4.86, FR-4, Dk 3.7
Internal Plane 2: plane copper 1.2, net (Multiple Nets)
Dielectric 2: core 5, FR-4, Dk 3.7
Signal Layer 3: signal copper 1.2
Dielectric 3: prepreg 6.28, FR-4, Dk 4.1
Signal Layer 4: signal copper 1.2
Dielectric 4: core 5, FR-4, Dk 3.7
Internal Plane 5: plane copper 1.2, net (Multiple Nets)
Dielectric 5: prepreg 5.12, FR-4, Dk 3.7
Internal Plane 6: plane copper 1.2, net (Multiple Nets)
Dielectric 6: core 5, FR-4, Dk 3.7
Signal Layer 7: signal copper 1.2
Dielectric 7: prepreg 6.28, FR-4, Dk 4.1
Signal Layer 8: signal copper 1.2
Dielectric 8: core 5, FR-4, Dk 3.7
Internal Plane 9: plane copper 1.2, net (Multiple Nets)
Dielectric 9: prepreg 4.86, FR-4, Dk 3.7
Bottom: signal copper 1.45
Bottom Solder: solder mask 0.8, Solder Resist, Dk 3.6

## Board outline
112.46,236 112.46,314 cw(c112.98,314) 112.98,314.52 128.94,314.52 cw(c128.98,314) 129.29,314.41 ccw(c152.53,345.09) 191.01,345.09 ccw(c152.53,345.09) 190.99,346.49 cw(c190.98,347) 190.46,347 190.46,479.49 0,479.49 cw(c0,480) -0.52,480 -0.52,2369.99 cw(c0,2369.99) 0,2370.51 1703.62,2370.51 cw(c1703.62,2369.99) 1703.99,2370.35 1724.1,2350.24 cw(c1723.73,2349.88) 1724.25,2349.88 1724.25,2305.27 ccw(c1742.37,2305.63) 1742,2287.51 ccw(c1741.78,2304.39) 1758.65,2304.39 ccw(c1741.78,2304.39) 1758.65,2304.59 ccw(c1741.78,2304.39) 1758.65,2304.6 1758.65,2349.88 cw(c1759.17,2349.88) 1758.8,2350.24 1778.49,2369.93 cw(c1778.85,2369.56) 1778.85,2370.08 1891.06,2370.08 cw(c1891.06,2369.56) 1891.42,2369.93 1911.11,2350.24 cw(c1910.74,2349.88) 1911.26,2349.88 1911.26,2304.6 cw(c1910.74,2304.6) 1911.26,2304.59 cw(c1928.17,2304.43) 1911.26,2304.6 1911.26,2304.59 ccw(c1928.17,2304.43) 1928,2287.51 ccw(c1928.17,2304.43) 1928.01,2287.51 cw(c1928,2287) 1928.02,2287.51 cw(c1928.29,2304.89) 1928.01,2287.51 ccw(c1928,2287) 1928,2287.51 1928.02,2287.51 ccw(c1928.29,2304.89) 1945.66,2304.6 ccw(c1928.29,2304.89) 1945.66,2304.61 ccw(c1928.29,2304.89) 1945.66,2304.61 1945.66,2304.6 1945.66,2349.88 cw(c1946.18,2349.88) 1945.81,2350.24 1965.93,2370.36 cw(c1966.3,2370) 1966.3,2370.52 4163.98,2370.52 cw(c4163.98,2370) 4164.49,2370 4164.49,236.1 cw(c4163.98,236.1) 4163.98,235.59 4099.08,235.59 4099.08,4 cw(c4098.57,4) 4098.57,3.49 3103.29,3.49 cw(c3103.29,4) 3102.77,4 3102.77,479.49 2453.49,479.49 2453.49,346.52 cw(c2453.48,346) 2453.99,346 ccw(c2492.48,346.12) 2515.62,315.37 cw(c2515.98,315) 2515.98,315.52 2531.98,315.52 cw(c2531.98,315) 2532.49,315 2532.49,236 cw(c2531.98,236) 2531.98,235.49 2355.49,235.49 2355.49,0 cw(c2354.98,0) 2354.98,-0.51 1306.09,-0.51 cw(c1306.09,0) 1305.57,0 1305.57,197 ccw(c1259.09,197) 1212.6,197 1212.6,0 cw(c1212.09,0) 1212.09,-0.51 289.98,-0.51 cw(c289.98,0) 289.46,0 289.46,235.49 112.98,235.49 cw(c112.98,236)

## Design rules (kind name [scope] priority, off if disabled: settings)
AcuteAngle [All] p1: minimum=4.50000000000000E+0001 checktracksonly=FALSE
AssemblyTestPointUsage [All] p1: valid=2
BoardOutlineClearance "Edge exception" [OnCopper and Not InComponentClass('Logo') and not InComponentClass('FiducialMark') and not InRegion(1000,500,4000,800) and not InPoly and ((Name = 'EC2') or (Name = 'EC1'))] p1: gap=0 ignorepadtopadclearanceinfootprint=FALSE
BoardOutlineClearance BoardOutlineClearance_1 [All] p2: gap=30 ignorepadtopadclearanceinfootprint=FALSE except(15: Arc-OutlineEdge Track-OutlineEdge SMDPad-OutlineEdge Fill-OutlineEdge)
BoardOutlineClearance BoardOutlineClearance_MountingHoles [OnCopper and InComponentClass('Mounting Holes')] p3: gap=40 ignorepadtopadclearanceinfootprint=FALSE
BoardOutlineClearance BoardOutlineClearance_Poly [OnCopper and IsPoly] p4: gap=25 ignorepadtopadclearanceinfootprint=FALSE
Clearance same_net [All] p1: gap=0 ignorepadtopadclearanceinfootprint=TRUE except(5.3: SMDPad-Via; 10: THPad-Via)
Clearance Clearance_Keepouts [((IsTrack Or IsArc) And Not InPoly) And IsFree and IsKeepOut vs ((IsTrack Or IsArc) And Not InPoly) And IsFree and IsKeepOut] p2: gap=0 ignorepadtopadclearanceinfootprint=FALSE
Clearance Clearance_Poly [InPolygon] p3: gap=8 ignorepadtopadclearanceinfootprint=FALSE
Clearance Clearance_FiducialMark [IsKeepOut and InComponentClass('FiducialMark') vs IsPad and InComponentClass('FiducialMark')] p4: gap=0 ignorepadtopadclearanceinfootprint=FALSE
Clearance [All] p5: gap=5.3 ignorepadtopadclearanceinfootprint=FALSE except(4: Arc-Via Track-Via; 5: SMDPad-Via Via-Via; 6: Arc-THPad Arc-Hole Track-THPad Track-Hole SMDPad-THPad THPad-THPad THPad-Via THPad-Fill THPad-Poly THPad-Region THPad-Text; 10: SMDPad-Hole THPad-Hole Via-Hole Fill-Hole Poly-Hole Region-Hole Text-Hole)
ComponentClearance ComponentClearance_MountingHoles_FiducialMarks [InComponentClass('Mounting Holes') vs InComponentClass('FiducialMark')] p1: gap=50 collisioncheckmode=3 verticalgap=10 showdistances=FALSE
ComponentClearance ComponentClearance_Shunt [InComponentClass('Header') vs InComponentClass('Shunt')] p2: gap=0 collisioncheckmode=3 verticalgap=0 showdistances=FALSE
ComponentClearance ComponentClearance_Logo [InComponentClass('Logo')] p3: gap=50 collisioncheckmode=3 verticalgap=10 showdistances=FALSE
ComponentClearance ComponentClearance_ScrewToNut [(HasFootprint('NY PMS 440 0025 PH')) vs (HasFootprint('Keystone_1902C'))] p4: gap=5 collisioncheckmode=3 verticalgap=10 showdistances=FALSE
ComponentClearance ComponentClearance_MountingHoles [InComponentClass('Mounting Holes')] p5: gap=250 collisioncheckmode=3 verticalgap=100000 showdistances=FALSE
ComponentClearance ComponentClearance_SmallPassives [HasFootprint('0201*') or HasFootprint('0402*') or HasFootprint('0508') or HasFootprint('0603*') or HasFootprint('0612') or HasFootprint('0805*') or HasFootprint('0815*') or HasFootprint('0830*') or HasFootprint('1206*') or HasFootprint('1210*') or HasFootprint('1808*') or HasFootprint('1812*') or HasFootprint('1825*') or HasFootprint('2010*') or HasFootprint('2220*') or HasFootprint('2225*') or HasFootprint('2512*') or HasFootprint('2728*') or HasFootprint('3518*') vs HasFootprint('0201*') or HasFootprint('0402*') or HasFootprint('0508') or HasFootprint('0603*') or HasFootprint('0612') or HasFootprint('0805*') or HasFootprint('0815*') or HasFootprint('0830*') or HasFootprint('1206*') or HasFootprint('1210*') or HasFootprint('1808*') or HasFootprint('1812*') or HasFootprint('1825*') or HasFootprint('2010*') or HasFootprint('2220*') or HasFootprint('2225*') or HasFootprint('2512*') or HasFootprint('2728*') or HasFootprint('3518*')] p6: gap=14.96 collisioncheckmode=3 verticalgap=10 showdistances=FALSE
ComponentClearance ComponentClearance_THtoSMT [IsThruComponent vs IsSMTComponent] p7: gap=40 collisioncheckmode=3 verticalgap=30 showdistances=FALSE
ComponentClearance ComponentClearance_THtoTH [IsThruComponent vs IsThruComponent] p8: gap=30 collisioncheckmode=3 verticalgap=30 showdistances=FALSE
ComponentClearance [All] p9: gap=30 collisioncheckmode=3 verticalgap=10 showdistances=FALSE
DiffPairsRouting [InDifferentialPairClass('All Differential Pairs')] p1: maxlimit=7 minlimit=6 mostfreqgap=7 toplayer_maxgap=6 toplayer_prefgap=6 toplayer_minwidth=4 toplayer_maxwidth=6.1 toplayer_prefwidth=6 midlayer1_mingap=7 midlayer1_minwidth=4 midlayer1_maxwidth=5 midlayer1_prefwidth=5 midlayer2_mingap=7 midlayer2_minwidth=4 midlayer2_maxwidth=5 midlayer2_prefwidth=5 midlayer3_mingap=7 midlayer3_minwidth=4 midlayer3_maxwidth=5 midlayer3_prefwidth=5 midlayer4_mingap=7 midlayer4_minwidth=4 midlayer4_maxwidth=5 midlayer4_prefwidth=5 bottomlayer_maxgap=6 bottomlayer_prefgap=6 bottomlayer_minwidth=4 bottomlayer_maxwidth=6 bottomlayer_prefwidth=6 maxuncoupledlength=1000
DiffPairsRouting DiffPairsRouting_90 [InDifferentialPairClass('All Differential Pairs')] p2: maxlimit=6 minlimit=5 mostfreqgap=6 toplayer_maxgap=5 toplayer_prefgap=5 toplayer_minwidth=7 toplayer_maxwidth=7 toplayer_prefwidth=7 midlayer1_mingap=6 midlayer1_minwidth=6 midlayer1_maxwidth=6 midlayer1_prefwidth=6 midlayer2_mingap=6 midlayer2_minwidth=6 midlayer2_maxwidth=6 midlayer2_prefwidth=6 midlayer3_mingap=6 midlayer3_minwidth=6 midlayer3_maxwidth=6 midlayer3_prefwidth=6 midlayer4_mingap=6 midlayer4_minwidth=6 midlayer4_maxwidth=6 midlayer4_prefwidth=6 bottomlayer_maxgap=5 bottomlayer_prefgap=5 bottomlayer_minwidth=7 bottomlayer_maxwidth=7 bottomlayer_prefwidth=7 maxuncoupledlength=1000
FabricationTestPointUsage TestPointUsage [All] p1: valid=2 allowmultiple=FALSE
FabricationTestpoint Testpoint [All] p1: side=3 testpointundercomponent=TRUE minsize=40 maxsize=100 preferedsize=60 minholesize=0 maxholesize=40 preferedholesize=32 testpointgrid=1 allowsidetop=TRUE allowsidebottom=TRUE usegrid=TRUE gridtolerance=0.01
FanoutControl Fanout_LCC [IsLCC] p1: bgadir=Out bgaviamode=Centered fanoutstyle=Auto fanoutdirection=Alternating viagrid=1 // Fanout_LCC (Default Rule)
FanoutControl Fanout_BGA [IsBGA] p2: bgadir=Out bgaviamode=Centered fanoutstyle=Auto fanoutdirection=Alternating viagrid=1 // Fanout_BGA (Default Rule)
FanoutControl Fanout_Default [All] p4: bgadir=Out bgaviamode=Centered fanoutstyle=Auto fanoutdirection=Alternating viagrid=1 // Fanout_Default (Default Rule)
FanoutControl Fanout_Small [(CompPinCount < 5)] p5: bgadir=Out bgaviamode=Centered fanoutstyle=Auto fanoutdirection=OutThenIn viagrid=1 // Fanout_Small (Default Rule)
HoleSize [All] p1: absolutevalues=TRUE maxlimit=251 minlimit=7.87 maxpercent=80.000 minpercent=20.000
MinimumAnnularRing MinimumAnnularRing_ThermalPadVias [IsVia and InAnyComponent] p1: minimumring=5
MinimumAnnularRing [All] p2: minimumring=5
MinimumSolderMaskSliver MinimumSolderMaskSliver_Logo [InComponentClass('Logo') vs InComponentClass('Logo')] p1: minsoldermaskwidth=0.7
MinimumSolderMaskSliver [All] p2: minsoldermaskwidth=3.94
PlaneClearance [All] p1: clearance=10
PlaneConnect [All] p1: planeconnectstyle=Direct reliefexpansion=10 reliefentries=4 reliefconductorwidth=10 reliefairgap=10
PolygonConnect [All] p1: connectstyle=Relief reliefconductorwidth=10 reliefentries=4 polygonreliefangle="90 Angle" airgapwidth=10
RoutingVias [All] p1: holewidth=8 width=22 viastyle="Through Hole" minholewidth=7.87 minwidth=18 maxholewidth=8 maxwidth=22
SilkToBoardRegionClearance [Not ((IsComment or IsDesignator) And (Hide <> 'False')) and not InRegion(1000,500,4000,800)] p1:
SilkToSilkClearance SilkToSilkClearance_Pb-FreeLogo [(HasFootprint('Pb-Free_Overlay_Medium') OR HasFootprint('Pb-Free_Overlay_Small')) vs (HasFootprint('Pb-Free_Overlay_Medium') OR HasFootprint('Pb-Free_Overlay_Small'))] p1: silktosilkclearance=1
SilkToSilkClearance [All] p2: silktosilkclearance=3
SilkToSolderMaskClearance SilkToComponentPadClearance [(IsPad or IsFill or IsRegion) and InAnycomponent] p1: minsilkscreentomaskgap=3 clearancetoexposedcopper=TRUE
SilkToSolderMaskClearance "Silk to Solder Mask Opening" [All] p2: minsilkscreentomaskgap=3 clearancetoexposedcopper=FALSE
SolderMaskExpansion [All] p1: expansion=1.97 istentingtop=FALSE
Width USB_Width [InNetClass('USB')] p1: maxlimit=6.1 minlimit=6.1 preferedwidth=6.1 checkconnectedcopper=TRUE
Width [All] p2: maxlimit=20 minlimit=4 preferedwidth=6.25 checkconnectedcopper=TRUE
14 further rules are at their usual default settings.

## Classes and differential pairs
component class MCU063A_Emulator_interface: C20:A C21:A C22:A C23:A C24:A C25:A C26:A C27:A C28:A C29:A R15:A S1:A U5:A U6:A U7:A U8:A U9:A
component class MCU063A_GPIO: EC2 R1 R2 R3 R4 R5 R6 R7 R8
component class Logo: Logo2 Logo5
component class MCU063A_EVM_Hardware: FID1 FID2 FID3 FID4 FID5 FID6 LBL1 Logo1 Logo2 Logo3 Logo4 Logo5 ZZ1 ZZ2 ZZ3 ZZ4
component class FiducialMark: FID1 FID2 FID3 FID4 FID5 FID6
component class AssemblyNote: ZZ1 ZZ2 ZZ3 ZZ4
component class Label: LBL1
component class Header: J2
component class MCU063A_ADC: C8 C9 C10 C11 C12 C13 C14 C15 C16 C17 C18 C19 C20 C21 C22 C23 C24 C25 C26 C27 C28 C29 C30 C31 C32 C33 C34 C35 C36 C37 C38 C39 C40 C41 C42 C43 C44 R44 R45 R46 R47 R48 R49 R50 R51 R52 R53 R54 R55 R56 R57 R58 R59 R60 R61 R62 R63 R64 R65 R66 R67 R68 R69 R70 R71 R72 R73 R74 R75 R76 R77 R78 S3 S4 U1 U6 U7 U8 U9 U10 U11 U12 U13
component class MCU063A_Emulator: C1:A C2:A C3:A C4:A C5:A C6:A C7:A C8:A C9:A C10:A C11:A C12:A C13:A C14:A C15:A C16:A C17:A C18:A C19:A C140 C141 C142 C143 C144 C145 C146 C147 C148 C149 C150 C151 C152 C153 C154 C155 D1:A D2:A D3:A D4:A D9 D10 D11 D12 J1:A J7 L1:A L2:A L6 L7 R1:A R2:A R3:A R4:A R5:A R6:A R7:A R8:A R9:A R10:A R11:A R12:A R13:A R14:A R158 R159 R160 R161 R162 R163 R164 R165 R166 R167 R168 R169 R170 TP1:A TP2:A TP3:A U1:A U2:A U3:A U4:A U22 U23 U24 U25 Y1:A Y3
component class MCU063A_EtherCAT: C104 C105 C106 C107 C108 C109 C110 C111 C112 C113 C114 C115 C116 C117 C118 C119 C120 C121 C122 C123 C124 C125 C126 C127 C128 C129 C130 C131 C132 C133 C134 C135 C136 C137 C138 C139 D7 D8 J5 J6 R114 R115 R116 R117 R118 R119 R120 R121 R122 R123 R124 R125 R126 R127 R128 R129 R130 R131 R132 R133 R134 R135 R136 R137 R138 R139 R140 R141 R142 R143 R144 R145 R146 R147 R148 R149 R150 R151 R152 R153 R154 R155 R156 R157 U18 U19 U20 U21
component class MCU063A_EtherNET: C87 C88 C89 C90 C91 C92 C93 C94 C95 C96 C97 C98 C99 C100 C101 C102 C103 J4 R103 R104 R105 R106 R107 R108 R109 R110 R111 R112 R113 U17
component class MCU063A_Power: C45 C46 C47 C48 C49 C50 C51 C52 C53 C54 C55 C56 C57 C58 C59 C60 C61 C62 C63 C64 C65 C66 C67 C68 C69 C70 C71 C72 C73 C74 C75 C76 C77 C78 C79 C80 C81 C82 D3 D4 D5 L1 L2 L3 L4 L5 q R79 R80 R81 R82 R83 R84 R85 R86 R87 R88 R89 R90 TP7 TP8 TP9 TP10 U14
component class MCU063A_Support: C1 C2 C3 C4 C5 C6 C7 D1 D2 J1 J2 R9 R10 R11 R12 R13 R14 R15 R16 R17 R18 R19 R20 R21 R22 R23 R24 R25 R26 R27 R28 R29 R30 R31 R32 R33 R34 R35 R36 R37 R38 R39 R40 R41 R42 R43 S1 S2 TP1 TP2 TP3 TP4 TP5 TP6 U2 U3 U4 U5 Y1 Y2
component class MCU063A_USB: C83 C84 C85 C86 D6 J3 Q1 R91 R92 R93 R94 R95 R96 R97 R98 R99 R100 R101 R102 U15 U16
net class USB: USB_N USB_P
differential pair ADC_IN1415: +ADC_IN1415_P -ADC_IN1415_N
differential pair ADC_D4D5: +ADC_D4D5_P -ADC_D4D5_N
differential pair ADC_D2D3: +ADC_D2D3_P -ADC_D2D3_N
differential pair ADC_D0D1: +ADC_D0D1_P -ADC_D0D1_N
differential pair ADC_C4C5: +ADC_C4C5_P -ADC_C4C5_N
differential pair ADC_C2C3: +ADC_C2C3_P -ADC_C2C3_N
differential pair ADC_B4B5: +ADC_B4B5_P -ADC_B4B5_N
differential pair ADC_B2B3: +ADC_B2B3_P -ADC_B2B3_N
differential pair ADC_B0B1: +ADC_B0B1_P -ADC_B0B1_N
differential pair ADC_A4A5: +ADC_A4A5_P -ADC_A4A5_N
differential pair ADC_A2A3: +ADC_A2A3_P -ADC_A2A3_N
differential pair ADC_A0A1: +ADC_A0A1_P -ADC_A0A1_N
differential pair P1_TD: +P1_TD_P -P1_TD_N
differential pair P1_RD: +P1_RD_P -P1_RD_N
differential pair P0_TD: +P0_TD_P -P0_TD_N
differential pair P0_RD: +P0_RD_P -P0_RD_N
differential pair RD: +RD_P -RD_N
differential pair TD: +TD_P -TD_N
differential pair USB: +USB_P -USB_N
differential pair 1415: +1415_P -1415_N
differential pair A0A1: +A0A1_P -A0A1_N
differential pair A2A3: +A2A3_P -A2A3_N
differential pair A4A5: +A4A5_P -A4A5_N
differential pair B0B1: +B0B1_P -B0B1_N
differential pair B2B3: +B2B3_P -B2B3_N
differential pair B4B5: +B4B5_P -B4B5_N
differential pair C2C3: +C2C3_P -C2C3_N
differential pair C4C5: +C4C5_P -C4C5_N
differential pair D0D1: +D0D1_P -D0D1_N
differential pair D2D3: +D2D3_P -D2D3_N
differential pair D4D5: +D4D5_P -D4D5_N

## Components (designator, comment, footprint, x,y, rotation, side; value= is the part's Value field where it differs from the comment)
C1 "CL05B104KP5NNNC" 0402 1995.01,1630 r90 bottom value=0.1uF
C1:A "CL05B104KP5NNNC" 0402 552.16,1876.61 r180 top value=0.1uF
C2 "CL05B104KP5NNNC" 0402 2390.01,2080 r180 top value=0.1uF
C2:A "C0603C475K9PACTU" 0603 522.97,2251.02 r180 bottom value=4.7uF
C3 "C0402C103J5RACTU" 0402 2148.63,2020 r180 top value=0.01uF
C3:A "C0603C475K9PACTU" 0603 560.03,1938.74 r0 top value=4.7uF
C4 "CL05B104KP5NNNC" 0402 1985.01,1885 r90 top value=0.1uF
C4:A "0402ZC103KAT2A" 0402 827.16,2241.61 r270 top value=0.01uF
C5 "C0402C103J5RACTU" 0402 1955.01,2060 r90 top value=0.01uF
C5:A "C0603C475K9PACTU" 0603 272.16,1756.61 r270 top value=4.7uF
C6 "CL05B104KP5NNNC" 0402 2230.01,1890 r90 top value=0.1uF
C6:A "CL05B104KP5NNNC" 0402 602.16,1806.61 r180 top value=0.1uF
C7 "CL05B104KP5NNNC" 0402 3439.9,388.6 r0 bottom value=0.1uF
C7:A "CL05B104KP5NNNC" 0402 274.77,1403.83 r90 top value=0.1uF
C8 "C0603C104K8RACTU" 0603 264.94,866.31 r90 bottom value=0.1uF
C8:A "CL05B104KP5NNNC" 0402 631.96,1451.77 r180 top value=0.1uF
C9 "C0603C104K8RACTU" 0603 572.21,885.31 r90 bottom value=0.1uF
C9:A "CL05B104KP5NNNC" 0402 720.66,1640.51 r90 top value=0.1uF
C10 "C0603C104K8RACTU" 0603 882.21,880.31 r90 bottom value=0.1uF
C10:A "CL05B104KP5NNNC" 0402 272.16,1531.61 r90 top value=0.1uF
C11 "C0603C105Z9VACTU" 0603 1384.92,427.12 r180 bottom value=1uF
C11:A "CL05B104KP5NNNC" 0402 727.16,1471.61 r270 top value=0.1uF
C12 "C0603C105Z9VACTU" 0603 1399.92,672.12 r180 bottom value=1uF
C12:A "CL05B104KP5NNNC" 0402 492.32,1353.11 r180 top value=0.1uF
C13 "C0603C104K8RACTU" 0603 1219.92,517.12 r270 bottom value=0.1uF
C13:A "C0603C475K9PACTU" 0603 762.5,2074.42 r90 bottom value=4.7uF
C14 "C0603C225K9PACTU" 0603 1154.92,517.12 r270 bottom value=2.2uF
C14:A "CL05B104KP5NNNC" 0402 147.16,1671.61 r180 bottom value=0.1uF
C15 "C0603C105Z9VACTU" 0603 1284.92,517.12 r90 bottom value=1uF
C15:A "C0603C475K9PACTU" 0603 377.16,1976.61 r180 bottom value=4.7uF
C16 "C0603C331J5GACTU" 0603 227.21,720.31 r90 bottom value=330pF
C16:A "CL05B104KP5NNNC" 0402 397.16,1911.61 r0 bottom value=0.1uF
C17 "C0603C331J5GACTU" 0603 224.21,900.31 r90 top value=330pF
C17:A "CGA2B2X7R1H332K050BA" 0402 148.08,2106.02 r180 bottom value=3300pF
C18 "C0603C331J5GACTU" 0603 537.21,720.31 r90 bottom value=330pF
C18:A "C0402C270J5GACTU" 0402 237.74,1906.61 r270 bottom value=27pF
C19 "C0603C331J5GACTU" 0603 537.21,900.31 r90 top value=330pF
C19:A "C0402C270J5GACTU" 0402 88.85,1715.15 r90 top value=27pF
C20 "C0603C331J5GACTU" 0603 377.21,720.31 r90 bottom value=330pF
C20:A "CL05B104KP5NNNC" 0402 826.96,2268.77 r90 bottom value=0.1uF
C21 "C0603C331J5GACTU" 0603 377.21,900.31 r90 top value=330pF
C21:A "CL05B104KP5NNNC" 0402 1271.96,2236.77 r270 bottom value=0.1uF
C22 "C0603C331J5GACTU" 0603 692.21,720.31 r90 bottom value=330pF
C22:A "CL05B104KP5NNNC" 0402 905,1778.62 r90 top value=0.1uF
C23 "C0603C331J5GACTU" 0603 692.21,900.31 r90 top value=330pF
C23:A "CL05B104KP5NNNC" 0402 1188.79,1997.76 r270 bottom value=0.1uF
C24 "C0603C331J5GACTU" 0603 1002.21,720.31 r90 bottom value=330pF
C24:A "CL05B104KP5NNNC" 0402 1620.01,2080 r90 top value=0.1uF
C25 "C0603C331J5GACTU" 0603 1002.21,900.31 r90 top value=330pF
C25:A "CL05B104KP5NNNC" 0402 958.34,1777.37 r90 top value=0.1uF
C26 "C0603C331J5GACTU" 0603 847.21,720.31 r90 bottom value=330pF
C26:A "CL05B104KP5NNNC" 0402 1185.03,1784.85 r270 top value=0.1uF
C27 "C0603C331J5GACTU" 0603 847.21,900.31 r90 top value=330pF
C27:A "CL05B104KP5NNNC" 0402 941.82,1410.32 r90 bottom value=0.1uF
C28 "GRM188R61A226ME15D" 0603 1507.09,536.41 r270 bottom value=22uF
C28:A "CL05B104KP5NNNC" 0402 1178.04,1410.32 r270 bottom value=0.1uF
C29 "GRM188R61A226ME15D" 0603 1790.55,536.41 r270 bottom value=22uF
C29:A "C1812C100JHGACTU" 1812_180 1068.18,2222.63 r180 bottom value=10pF
C30 "GRM188R61A226ME15D" 0603 1349.61,945.86 r180 bottom value=22uF
C31 "GRM188R61A226ME15D" 0603 1617.33,536.41 r270 bottom value=22uF
C32 "C0603C331J5GACTU" 0603 142.21,720.31 r90 bottom value=330pF
C33 "C0603C331J5GACTU" 0603 139.21,900.31 r90 top value=330pF
C34 "C0603C331J5GACTU" 0603 457.21,720.31 r90 bottom value=330pF
C35 "C0603C331J5GACTU" 0603 457.21,900.31 r90 top value=330pF
C36 "C0603C331J5GACTU" 0603 292.21,720.31 r90 bottom value=330pF
C37 "C0603C331J5GACTU" 0603 292.21,900.31 r90 top value=330pF
C38 "C0603C331J5GACTU" 0603 602.21,720.31 r90 bottom value=330pF
C39 "C0603C331J5GACTU" 0603 602.21,900.31 r90 top value=330pF
C40 "C0603C331J5GACTU" 0603 912.21,720.31 r90 bottom value=330pF
C41 "C0603C331J5GACTU" 0603 912.21,900.31 r90 top value=330pF
C42 "C0603C331J5GACTU" 0603 757.21,720.31 r90 bottom value=330pF
C43 "C0603C331J5GACTU" 0603 757.21,900.31 r90 top value=330pF
C44 "C0603C104K8RACTU" 0603 1250.01,798.62 r270 bottom value=0.1uF
C45 "GRM21BR61C226ME44L" 0805_HV 3207.92,876.38 r270 bottom value=22uF
C46 "0402YC104KAT2A" 0402 3733.73,943.17 r270 bottom value=0.1uF
C47 "GRM21BR61C226ME44L" 0805_HV 3816.2,943.17 r270 bottom value=22uF
C48 "0402YC104KAT2A" 0402 3542.92,1146.38 r180 bottom value=0.1uF
C49 "0402YC104KAT2A" 0402 3572.92,776.38 r90 bottom value=0.1uF
C50 "885012005043" 0402 3302.92,1131.38 r90 bottom value=33pF
C51 "GRM21BR61C226ME44L" 0805_HV 3207.92,1066.38 r90 bottom value=22uF
C52 "C0603C225K8PACTU" 0603 2575.01,915 r180 bottom value=2.2uF
C53 "C0603C225K8PACTU" 0603 2255.12,1040.35 r180 bottom value=2.2uF
C54 "0402YC104KAT2A" 0402 1640.95,1040.35 r180 bottom value=0.1uF
C55 "0402YC104KAT2A" 0402 1963.78,1111.22 r90 bottom value=0.1uF
C56 "0402YC104KAT2A" 0402L 1877.17,882.87 r90 bottom value=0.1uF
C57 "0402YC104KAT2A" 0402 1948.03,945.86 r180 bottom value=0.1uF
C58 "0402YC104KAT2A" 0402 1798.43,1166.34 r180 bottom value=0.1uF
C59 "0402YC104KAT2A" 0402 1877.17,1245.08 r90 bottom value=0.1uF
C60 "0402YC104KAT2A" 0402 1948.03,1040.35 r180 bottom value=0.1uF
C61 "0402YC104KAT2A" 0402 1751.18,969.49 r90 bottom value=0.1uF
C62 "0402YC104KAT2A" 0402L 1822.05,945.86 r0 bottom value=0.1uF
C63 "C0603C225K8PACTU" 0603 2231.5,536.41 r90 bottom value=2.2uF
C64 "C0603C225K8PACTU" 0603 2066.14,646.65 r180 top value=2.2uF
C65 "0402YC104KAT2A" 0402 1475.59,993.11 r180 bottom value=0.1uF
C66 "0402YC104KAT2A" 0402 1837.8,670.27 r270 bottom value=0.1uF
C67 "0402YC104KAT2A" 0402 2231.5,788.38 r0 bottom value=0.1uF
C68 "0402YC104KAT2A" 0402 2081.89,1040.35 r0 bottom value=0.1uF
C69 "0402YC104KAT2A" 0402 1877.17,761.38 r270 bottom value=0.1uF
C70 "0402YC104KAT2A" 0402 1815.01,1420 r90 bottom value=0.1uF
C71 "0402YC104KAT2A" 0402 1499.21,1323.82 r180 bottom value=0.1uF
C72 "0402YC104KAT2A" 0402 2129.14,1418.3 r90 bottom value=0.1uF
C73 "0402YC104KAT2A" 0402 1751.18,1087.6 r270 bottom value=0.1uF
C74 "0402YC104KAT2A" 0402 1469.21,1197.83 r180 bottom value=0.1uF
C75 "0402YC104KAT2A" 0402 1892.92,1166.34 r180 bottom value=0.1uF
C76 "0402YC104KAT2A" 0402 1870.01,1420 r90 bottom value=0.1uF
C77 "0402YC104KAT2A" 0402 2231.5,1134.84 r0 bottom value=0.1uF
C78 "0402YC104KAT2A" 0402 1469.21,1150.59 r180 bottom value=0.1uF
C79 "0402YC104KAT2A" 0402 1822.05,1040.35 r0 bottom value=0.1uF
C80 "0402YC104KAT2A" 0402 1469.21,1103.34 r180 bottom value=0.1uF
C81 "C0805C106K8PACTU" 0805_HV 2380.01,1460 r270 top value=10uF
C82 "GRM188R61A106ME69D" 0603 2265,1230 r270 top value=10uF
C83 "C0603C475K9PACTU" 0603 1840.01,1760 r0 bottom value=4.7uF
C84 "293D104X9035A2TE3" 3216-18 1497.61,1837.8 r180 bottom value=0.1uF
C85 "TLJA686M010R1500" 3216-18 1497.61,1732.8 r180 bottom value=68uF
C86 "CGA2B2X7R1H332K050BA" 0402 1860,2195 r180 bottom value=3300pF
C87 "CL05A106MQ5NUNC" 0402 2895.01,1550 r0 top value=10uF
C88 "EMK105BJ105KVHF" 0402 2895.01,1620 r180 top value=1uF
C89 "LMK105BJ104KV-F" 0402 2897.21,1705.31 r180 top value=0.1uF
C90 "885012205031" 0402 2895.01,1485 r0 top value=0.01uF
C91 "885012205031" 0402 2637.21,1405.31 r180 top value=0.01uF
C92 "LMK105BJ104KV-F" 0402 2752.21,1455.31 r0 top value=0.1uF
C93 "EMK105BJ105KVHF" 0402 2752.21,1405.31 r0 top value=1uF
C94 "CL05A106MQ5NUNC" 0402 2637.21,1455.31 r180 top value=10uF
C95 "LMK105BJ104KV-F" 0402 2895.01,1620 r180 bottom value=0.1uF
C96 "EMK105BJ105KVHF" 0402 2896.39,1550 r0 bottom value=1uF
C97 "EMK105BJ105KVHF" 0402 3035.01,1741.65 r90 top value=1uF
C98 "LMK105BJ104KV-F" 0402 2980.01,1590 r90 top value=0.1uF
C99 "EMK105BJ105KVHF" 0402 3035.01,1590 r90 top value=1uF
C100 "LMK105BJ104KV-F" 0402 2980.01,1741.65 r90 top value=0.1uF
C101 "LMK105BJ104KV-F" 0402 2895.01,1775 r180 bottom value=0.1uF
C102 "EMK105BJ105KVHF" 0402 2895.01,1710 r180 bottom value=1uF
C103 "12061C472KAT2A" 1206 3695.01,2135 r0 bottom value=4700pF
C104 "CL05A106MQ5NUNC" 0402 2886.21,2080 r0 bottom value=10uF
C105 "EMK105BJ105KVHF" 0402 2888.2,2010 r0 bottom value=1uF
C106 "LMK105BJ104KV-F" 0402 2890.01,2155 r0 bottom value=0.1uF
C107 "885012205031" 0402 2895.01,1915 r0 bottom value=0.01uF
C108 "885012205031" 0402 2630.01,2225 r180 top value=0.01uF
C109 "LMK105BJ104KV-F" 0402 2750.01,2170 r0 top value=0.1uF
C110 "EMK105BJ105KVHF" 0402 2750.01,2225 r0 top value=1uF
C111 "CL05A106MQ5NUNC" 0402 2630.01,2170 r180 top value=10uF
C112 "LMK105BJ104KV-F" 0402 2900.01,2080 r180 top value=0.1uF
C113 "EMK105BJ105KVHF" 0402 2900.01,2010 r180 top value=1uF
C114 "EMK105BJ105KVHF" 0402 3320.01,2145 r270 bottom value=1uF
C115 "CL05B104KP5NNNC" 0402 2165.01,1595 r90 top value=0.1uF
C116 "LMK105BJ104KV-F" 0402 3375.01,2145 r270 bottom value=0.1uF
C117 "EMK105BJ105KVHF" 0402 3430.01,2145 r270 bottom value=1uF
C118 "LMK105BJ104KV-F" 0402 3485.01,2145 r270 bottom value=0.1uF
C119 "LMK105BJ104KV-F" 0402 2895.01,1915 r180 top value=0.1uF
C120 "EMK105BJ105KVHF" 0402 2895.01,1845 r180 top value=1uF
C121 "12061C472KAT2A" 1206 3695.01,2245 r0 bottom value=4700pF
C122 "CL05A106MQ5NUNC" 0402 2895.21,989.31 r180 bottom value=10uF
C123 "EMK105BJ105KVHF" 0402 2857.21,1050.31 r180 bottom value=1uF
C124 "LMK105BJ104KV-F" 0402 2892.21,1100.31 r180 bottom value=0.1uF
C125 "885012205031" 0402 2892.21,1155.31 r180 bottom value=0.01uF
C126 "885012205031" 0402 2642.21,1300.31 r180 bottom value=0.01uF
C127 "LMK105BJ104KV-F" 0402 2757.21,1300.31 r0 bottom value=0.1uF
C128 "EMK105BJ105KVHF" 0402 2757.21,1245.31 r0 bottom value=1uF
C129 "CL05A106MQ5NUNC" 0402 2642.21,1245.31 r180 bottom value=10uF
C130 "LMK105BJ104KV-F" 0402 2895.01,1155 r180 top value=0.1uF
C131 "EMK105BJ105KVHF" 0402 2895.01,1085 r180 top value=1uF
C132 "EMK105BJ105KVHF" 0402 3027.21,1115.31 r180 bottom value=1uF
C133 "LMK105BJ104KV-F" 0402 3027.21,1065.31 r180 bottom value=0.1uF
C134 "CL05B104KP5NNNC" 0402 3510.01,1465 r180 top value=0.1uF
C135 "EMK105BJ105KVHF" 0402 3028.63,990 r180 bottom value=1uF
C136 "LMK105BJ104KV-F" 0402 3027.21,1165.31 r180 bottom value=0.1uF
C137 "LMK105BJ104KV-F" 0402 2895.01,990 r180 top value=0.1uF
C138 "EMK105BJ105KVHF" 0402 2895.01,910 r180 top value=1uF
C139 "12061C472KAT2A" 1206 3715.01,670 r0 bottom value=4700pF
D1 "150080SS75000" WL-SMCW_RED_0805 1845.01,1655 r90 top value=Red
D1:A "MBRM110ET1G" POWERMITE 522.16,2111.61 r90 top value=10V
D2 "150080SS75000" WL-SMCW_RED_0805 1950.01,1655 r90 top value=Red
D2:A "150080VS75000" WL-SMCW_Green_0805 697.54,2255.33 r180 top value="Bright Green"
D3 "MBRM110ET1G" POWERMITE 4013.71,916.38 r0 bottom value=10V
D3:A "150080BS75000" WL-SMCW_Blue_0805 82.16,1445.23 r90 top value=Blue
D4 "CFSH05-20L TR" SOD-882L 3301.11,971.38 r90 bottom value=20V
D4:A "150080BS75000" WL-SMCW_Blue_0805 178.95,1445.4 r90 top value=Blue
D5 "150080VS75000" WL-SMCW_Green_0805 3017.92,871.38 r270 bottom value="Bright Green"
D6 "MBRM110ET1G" POWERMITE 1588.31,2117.13 r0 bottom value=10V
D7 "150080SS75000" WL-SMCW_RED_0805 3477.21,2305.31 r180 top value=Red
D8 "150080VS75000" WL-SMCW_Green_0805 3272.21,2305.31 r180 top value="Bright Green"
EC1 "controlCARD-120HSEC_Edge" controlCARD-120HSEC_Edge 1258.86,-3.49 r0 top locked
EC2 "controlCARD-180HSEC-60pinAddon_Edge" controlCARD-180HSEC-60pinAddon_Edge 3597.35,-3.49 r0 top locked
FID1 "Fiducial" Fiducial10-20 112.21,1105.31 r180 bottom
FID2 "Fiducial" Fiducial10-20 2877.21,2300.31 r180 bottom
FID3 "Fiducial" Fiducial10-20 4090.01,470.7 r180 bottom
FID4 "Fiducial" Fiducial10-20 2877.21,2300.31 r90 top
FID5 "Fiducial" Fiducial10-20 112.21,1105.31 r90 top
FID6 "Fiducial" Fiducial10-20 4090.01,470.7 r90 top
J1 "2908-05WB-MG" 3M_2908-05WB-MG 2416.26,2170.31 r180 bottom
J1:A "65100516121" Wurth_65100516121 0.01,2070 r270 top
J2 "TMM-104-01-T-D" Samtec_TMM-104-01-x-D 2503.12,779.49 r90 top
J3 "1051640001" Molex_1051640001 1835,2370 r180 top
J4 "7498010210A" Wurth_7498010210A 3987.4,1697.72 r0 bottom
J5 "7498010210A" Wurth_7498010210A 3987.4,1925.4 r0 top
J6 "7498010210A" Wurth_7498010210A 3987.4,972.12 r0 top
L1 "PFL3215-222MEB" PFL3215 3432.92,846.11 r180 bottom value=2.2uH
L1:A "HZ0805E601R-10" 0805_HV 639.53,2082.06 r90 bottom value="600 ohm"
L2 "78438323033" WE-MAIA_2510 3447.92,996.16 r180 bottom value=3.3uH
L2:A "HZ0805E601R-10" 0805_HV 327.16,2056.61 r180 bottom value="600 ohm"
L3 "BKP2125HS600-T" 0805_HV 2420.01,915 r180 bottom value="60 ohm"
L4 "BKP2125HS600-T" 0805_HV 2113.39,567.91 r180 bottom value="60 ohm"
L5 "BLM21PG221SN1D" 0805_HV 2380.01,1295 r270 top value="220 ohm"
LBL1 "THT-14-423-10" Label_650x200 575,1125 r0 top
Logo1 "CE Mark" CE_Mark_5mm 469.21,1152.31 r180 bottom
Logo2 "Texas Instruments" TI_Stacked_Overlay_Small 3650,450 r0 top
Logo3 "FCC disclaimer" FCC_disclaimer 1780.01,365 r0 top
Logo4 "WEEE logo" WEEE_Minimum 763.21,1193.31 r180 bottom
Logo5 "ETHERCAT LABEL" EtherCAT_label 1084.2,1089.5 r0 top
Q1 "NTA7002NT1G" SOT-416 1670.01,1750 r90 bottom value=30V
R1 "CRCW04024K70JNED" 0402 270.01,425 r90 top value=4.7k
R1:A "CRCW0402680RJNED" 0402 673.43,2254.68 r180 bottom value=680
R2 "CRCW04024K70JNED" 0402 270.01,425 r270 bottom value=4.7k
R2:A "CRCW040210K0JNED" 0402 855,1615 r270 bottom value=10k
R3 "CRCW040239R0JNED" 0402 2267.25,977.36 r180 top value=39
R3:A "CRCW04020000Z0ED" 0402 661.96,1921.77 r90 bottom value=0
R4 "CRCW040239R0JNED" 0402 2267.25,1024.6 r180 top value=39
R4:A "CRCW040210K0JNED" 0402 836.96,1506.77 r0 bottom value=10k
R5 "CRCW040239R0JNED" 0402 2267.25,930.12 r180 top value=39
R5:A "CRCW04021K00JNED" 0402 837.16,1426.61 r0 bottom value=1.0k
R6 "CRCW040239R0JNED" 0402 2267.25,1071.85 r180 top value=39
R6:A "CRCW04021K00JNED" 0402 82.16,1421.61 r270 bottom value=1.0k
R7 "CRCW040239R0JNED" 0402 2097.64,1456.93 r270 top value=39
R7:A "CRCW04021K00JNED" 0402 182.16,1416.61 r270 bottom value=1.0k
R8 "CRCW040239R0JNED" 0402 2050.4,1456.93 r270 top value=39
R8:A "CRCW040210K0JNED" 0402 411.96,1446.77 r90 top value=10k
R9 "CRCW0402680RJNED" 0402 1835.01,1760 r0 top value=680
R9:A "CRCW04022K20JNED" 0402 336.95,1540.41 r90 top value=2.2k
R10 "CRCW0402680RJNED" 0402 1960.01,1760 r0 top value=680
R10:A "CRCW04021K00JNED" 0402 612.16,1926.61 r270 bottom value=1.0k
R11 "CRCW04021M50JNED" 0402 1795.01,1660 r270 bottom value=1.5Meg
R11:A "CRCW04020000Z0ED" 0402 147.16,2051.61 r0 bottom value=0
R12 "CRCW04021M50JNED" 0402 2025.01,1710 r0 bottom value=1.5Meg
R12:A "CRCW04020000Z0ED" 0402 196.96,1708.15 r270 top value=0
R13 "RC0402FR-0710KL" 0402 2360.01,2170 r270 top value=10.0k
R13:A "CRCW040212K0JNED" 0402 397.16,1861.61 r0 bottom value=12k
R14 "RC0402FR-0710KL" 0402 2416.26,2170.31 r270 top value=10.0k
R14:A "CRCW04020000Z0ED" 0402 622.16,1351.61 r180 top value=0
R15 "CRCW040239R0JNED" 0402 2025.01,515 r270 top value=39
R15:A "CRCW040210K0JNED" 0402 1560.01,2240 r270 bottom value=10k
R16 "CRCW04022K20JNED" 0402 2090.01,515 r90 top value=2.2k
R17 "CRCW04022K20JNED" 0402 2150.01,515 r90 top value=2.2k
R18 "RC0402FR-0710KL" 0402 2155.01,2075 r180 top value=10.0k
R19 "CRCW06030000Z0EA" 0603 2390.01,618.5 r270 top value=0
R20 "CRCW04022K20JNED" 0402 2260.01,2020 r0 top value=2.2k
R21 "CRCW06030000Z0EA" 0603 2467.14,618.5 r270 top value=0
R22 "CRCW06030000Z0EA" 0603 2543.57,618.5 r270 top value=0
R23 "CRCW06030000Z0EA" 0603 2620.01,620 r270 top value=0
R24 "CRCW040256K0JNED" 0402 1300.01,1735 r180 bottom value=56k
R25 "CRCW040256K0JNED" 0402 1300.01,1785 r0 bottom value=56k
R26 "CRCW04022K20JNED" 0402 1900.01,2060 r90 top value=2.2k
R27 "CRCW06030000Z0EA" 0603 1910.01,1880 r270 top value=0
R28 "CRCW06030000Z0EA" 0603 2863.71,583.7 r90 top value=0
R29 "CRCW04022K20JNED" 0402 1675.01,1730 r0 top value=2.2k
R30 "CRCW04022K20JNED" 0402 1675.01,1785 r180 top value=2.2k
R31 "CRCW06030000Z0EA" 0603 2863.71,583.7 r270 bottom value=0
R32 "CRCW06030000Z0EA" 0603 2955.01,585 r90 top value=0
R33 "CRCW06030000Z0EA" 0603 2955.01,585 r270 bottom value=0
R34 "CPF0402B10RE1" CPF0402 3436.1,566.8 r180 bottom value=10.0
R35 "CPF0402B10RE1" CPF0402 3205.32,535 r180 bottom value=10.0
R36 "CRCW06030000Z0EA" 0603 2781.31,583.35 r90 top value=0
R37 "CPF0402B10RE1" CPF0402 3205.01,425 r180 bottom value=10.0
R38 "CRCW04020000Z0EDHP" 0402 3760.01,540 r270 bottom value=0
R39 "CPF0402B10RE1" CPF0402 3205.01,481.57 r180 bottom value=10.0
R40 "CRCW06030000Z0EA" 0603 2781.31,583.35 r270 bottom value=0
R41 "CRCW04020000Z0EDHP" 0402 3501.71,643.5 r180 bottom value=0
R42 "CRCW04020000Z0EDHP" 0402 3940.01,545 r270 bottom value=0
R43 "CRCW04020000Z0EDHP" 0402 3346.71,643.5 r180 bottom value=0
R44 "CRCW06030000Z0EA" 0603 1399.92,552.12 r180 bottom value=0
R45 "CRCW06030000Z0EA" 0603 1399.92,492.12 r0 bottom value=0
R46 "RC0603FR-071KL" 0603 1399.92,612.12 r0 bottom value=1.00k
R47 "CRCW06030000Z0EA" 0603 1562.21,670.27 r90 bottom value=0
R48 "CRCW06030000Z0EA" 0603 336.42,437.87 r270 top value=0
R49 "CRCW06030000Z0EA" 0603 396.42,437.87 r270 top value=0
R50 "CRCW06030000Z0EA" 0603 456.42,437.87 r270 top value=0
R51 "CRCW06030000Z0EA" 0603 516.42,437.87 r270 top value=0
R52 "CRCW06030000Z0EA" 0603 576.42,437.87 r270 top value=0
R53 "CRCW06030000Z0EA" 0603 636.42,437.87 r270 top value=0
R54 "CRCW06030000Z0EA" 0603 1735.44,670.27 r90 bottom value=0
R55 "CRCW06030000Z0EA" 0603 696.42,437.87 r270 top value=0
R56 "CRCW06030000Z0EA" 0603 756.42,437.87 r270 top value=0
R57 "CRCW06030000Z0EA" 0603 336.42,437.87 r270 bottom value=0
R58 "CRCW06030000Z0EA" 0603 396.42,437.87 r270 bottom value=0
R59 "CRCW06030000Z0EA" 0603 456.42,437.87 r270 bottom value=0
R60 "CRCW06030000Z0EA" 0603 516.42,437.87 r270 bottom value=0
R61 "CRCW06030000Z0EA" 0603 576.42,437.87 r270 bottom value=0
R62 "CRCW06030000Z0EA" 0603 636.42,437.87 r270 bottom value=0
R63 "CRCW06030000Z0EA" 0603 1475.59,882.87 r0 bottom value=0
R64 "CRCW06030000Z0EA" 0603 816.42,437.87 r270 top value=0
R65 "CRCW06030000Z0EA" 0603 876.42,437.87 r270 top value=0
R66 "CRCW06030000Z0EA" 0603 936.42,437.87 r270 top value=0
R67 "CRCW06030000Z0EA" 0603 996.42,437.87 r270 top value=0
R68 "CRCW06030000Z0EA" 0603 1672.44,670.27 r90 bottom value=0
R69 "CRCW06030000Z0EA" 0603 696.42,437.87 r270 bottom value=0
R70 "CRCW06030000Z0EA" 0603 756.42,437.87 r270 bottom value=0
R71 "CRCW06030000Z0EA" 0603 816.42,437.87 r270 bottom value=0
R72 "CRCW06030000Z0EA" 0603 876.42,437.87 r270 bottom value=0
R73 "CRCW06030000Z0EA" 0603 936.42,437.87 r270 bottom value=0
R74 "ERJ2BWFR100X" 0402 1507.09,662.4 r270 bottom value=0.1
R75 "ERJ2BWFR100X" 0402 1790.55,670.27 r270 bottom value=0.1
R76 "ERJ2BWFR100X" 0402 1475.59,937.99 r180 bottom value=0.1
R77 "ERJ2BWFR100X" 0402 1617.33,670.27 r270 bottom value=0.1
R78 "CRCW06030000Z0EA" 0603 996.42,437.87 r270 bottom value=0
R79 "MCR10EZPJ000" 0805_HV 3952.17,1052.9 r0 bottom value=0
R80 "CRCW04020000Z0ED" 0402 3457.92,740.13 r0 bottom value=0
R81 "CRCW040222K0JNED" 0402 3663.39,1146.38 r0 bottom value=22k
R82 "MCR10EZPJ000" 0805_HV 3697.92,776.38 r180 bottom value=0
R83 "CRCW0402340KFKED" 0402 3297.92,836.38 r90 bottom value=340k
R84 "CRCW0402680RJNED" 0402 3115.24,881.38 r90 bottom value=680
R85 "ERJ-2RKF2001X" 0402 3272.92,736.38 r0 bottom value=2.00k
R86 "CRCW0402205KFKED" 0402 3372.92,1131.38 r270 bottom value=205k
R87 "CRCW040210K0JNED" 0402 3805.32,1078.17 r0 bottom value=10k
R88 "CRCW0603100KJNEA" 0603 3675.37,1076.71 r0 bottom value=100k
R89 "ERJ-2RKF2003X" 0402 3442.92,1131.38 r90 bottom value=200k
R90 "RT0603DRE0775KL" 0603 3137.92,736.38 r0 bottom value=75.0k
R91 "CRCW04020000Z0ED" 0402 1790.01,2060 r90 bottom value=0
R92 "CRCW04020000Z0ED" 0402 1845.01,2060 r90 bottom value=0
R93 "ERJ-6GEYJ103V" 0805_HV 1702.51,1983.66 r90 top value=10k
R94 "ERJ-6GEYJ103V" 0805_HV 1805.01,1875 r270 bottom value=10k
R95 "ERJ-6GEYJ103V" 0805_HV 1620.01,1610 r90 bottom value=10k
R96 "ERJ-6GEYJ103V" 0805_HV 1910.01,1875 r90 bottom value=10k
R97 "ERJ-6GEYJ103V" 0805_HV 1720.01,1610 r90 bottom value=10k
R98 "CRCW04020000Z0ED" 0402 1546.15,1961.61 r90 bottom value=0
R99 "ERJ-3GEYJ104V" 0603 1690.01,2100 r270 bottom value=100k
R100 "ERJ-3GEYJ104V" 0603 1980,2190 r180 bottom value=100k
R101 "ERJ-3GEYJ104V" 0603 1670.01,1830 r180 bottom value=100k
R102 "CRCW04020000Z0ED" 0402 1755,2195 r0 bottom value=0
R103 "RC0402FR-0749R9L" 0402 3006.39,1550 r180 bottom value=49.9
R104 "RC0402FR-0749R9L" 0402 3005.01,1620 r180 bottom value=49.9
R105 "CRCW04024K87FKED" 0402 2785.01,1605 r90 top value=4.87k
R106 "RC0402FR-0749R9L" 0402 3005.01,1710 r180 bottom value=49.9
R107 "RC0402FR-0749R9L" 0402 3006.39,1775 r180 bottom value=49.9
R108 "CRCW04022K20JNED" 0402 2700.92,1531.57 r0 top value=2.2k
R109 "RC0402FR-0710KL" 0402 2720.6,1720.55 r180 top value=10.0k
R110 "CRCW04022K49FKED" 0402 2595.01,1585 r90 top value=2.49k
R111 "CRCW04022K20JNED" 0402 3005.01,1485 r180 bottom value=2.2k
R112 "CRCW0603470RJNEA" 0603 3195.01,2130 r180 bottom value=470
R113 "CRCW0603470RJNEA" 0603 2990.01,1405 r0 bottom value=470
R114 "RC0402FR-0749R9L" 0402 3005.01,2080 r180 top value=49.9
R115 "RC0402FR-0749R9L" 0402 3005.01,2010 r180 top locked value=49.9
R116 "CRCW04024K70JNED" 0402 2145.01,1755 r180 top value=4.7k
R117 "CRCW04024K70JNED" 0402 2145.01,1700 r180 top value=4.7k
R118 "CRCW02012K20JNED" 0201 2495.01,2015 r180 top value=2.2k
R119 "CRCW02012K20JNED" 0201 2497.02,2055 r180 top value=2.2k
R120 "CRCW04024K87FKED" 0402 2784.5,2054.21 r270 bottom value=4.87k
R121 "RC0402FR-0749R9L" 0402 3005.01,1915 r180 top value=49.9
R122 "RC0402FR-0749R9L" 0402 3005.01,1845 r180 top value=49.9
R123 "CRCW04022K20JNED" 0402 2699.85,2099.49 r0 bottom value=2.2k
R124 "RC0402FR-0710KL" 0402 2699.85,1910.51 r180 bottom value=10.0k
R125 "CRCW0603470RJNEA" 0603 3105.01,1480 r90 top value=470
R126 "CRCW04022K49FKED" 0402 2697.21,2175.31 r180 bottom value=2.49k
R127 "CRCW02012K20JNED" 0201 2495.01,2095 r0 top value=2.2k
R128 "CRCW02012K20JNED" 0201 2495.01,1935 r0 top value=2.2k
R129 "CRCW02012K20JNED" 0201 2493,1895 r0 top value=2.2k
R130 "CRCW02012K20JNED" 0201 2495.01,1855 r0 top value=2.2k
R131 "CRCW02012K20JNED" 0201 2577.21,1825.31 r90 top value=2.2k
R132 "CRCW02012K20JNED" 0201 2495.01,1975 r0 top value=2.2k
R133 "CRCW04022K20JNED" 0402 3005.01,2160 r180 top value=2.2k
R134 "CRCW0603470RJNEA" 0603 2995.31,2230 r0 top value=470
R135 "RC0402FR-0749R9L" 0402 3005.01,1155 r180 top value=49.9
R136 "RC0402FR-0749R9L" 0402 3005.01,1085 r180 top value=49.9
R137 "CRCW04021K27FKED" 0402 3205.01,1400 r180 top value=1.27k
R138 "CRCW0402680RJNED" 0402 3205.01,1510 r0 top value=680
R139 "CRCW04021M50JNED" 0402 3785.01,1420 r0 top value=1.5Meg
R140 "CRCW04021M50JNED" 0402 3785.01,1500 r0 top value=1.5Meg
R141 "CRCW02012K20JNED" 0201 2475.01,1165 r180 top value=2.2k
R142 "CRCW02012K20JNED" 0201 2475.01,1085 r180 top value=2.2k
R143 "CRCW02012K20JNED" 0201 2475.01,1125 r180 top value=2.2k
R144 "CRCW04024K87FKED" 0402 2780.56,1086.97 r270 bottom value=4.87k
R145 "RC0402FR-0749R9L" 0402 3005.01,990 r180 top value=49.9
R146 "RC0402FR-0749R9L" 0402 3004.14,910.75 r180 top value=49.9
R147 "RC0402FR-0710KL" 0402 2721.39,985 r180 bottom value=10.0k
R148 "CRCW04022K20JNED" 0402 2751.39,1175 r180 bottom value=2.2k
R149 "CRCW0603470RJNEA" 0603 3060.01,620 r90 top value=470
R150 "CRCW04022K49FKED" 0402 2636.86,1175.55 r180 bottom value=2.49k
R151 "CRCW02012K20JNED" 0201 2475.01,1210 r0 top value=2.2k
R152 "CRCW02012K20JNED" 0201 2475.01,1045 r0 top value=2.2k
R153 "CRCW02012K20JNED" 0201 2475.01,1005 r0 top value=2.2k
R154 "CRCW02012K20JNED" 0201 2475.01,965 r0 top value=2.2k
R155 "CRCW02012K20JNED" 0201 2615.01,915 r90 top value=2.2k
R156 "CRCW04022K20JNED" 0402 3005.01,1255 r180 top value=2.2k
R157 "CRCW0603470RJNEA" 0603 3005.01,1320 r0 top value=470
S1 "B3U-1100P" SW_B3U-1100P 2200.01,2300 r180 top
S1:A "218-2LPST" SW_218-2LP 1425.01,2240 r0 top
S2 "218-2LPST" SW_218-2LP 1433.36,1761.81 r0 top
S3 "CAS-D20TA" SW_CAS-D20TA 1861.42,506.1 r90 top
S4 "CAS-D20TA" SW_CAS-D20TA 1586.42,506.1 r90 top
TP1 "TESTPOINT" TP_50MIL-25MILHOLE 2295.01,655 r90 top
TP1:A "TESTPOINT" TP_50MIL-25MILHOLE 950.01,1675 r90 top
TP2 "TESTPOINT" TP_50MIL-25MILHOLE 2015.01,2100 r180 top
TP2:A "TESTPOINT" TP_50MIL-25MILHOLE 950.01,1525 r90 top
TP3 "TESTPOINT" TP_50MIL-25MILHOLE 2015.01,2020 r180 top
TP3:A "TESTPOINT" TP_50MIL-25MILHOLE 950.01,1600 r90 top
TP4 "TESTPOINT" TP_50MIL-25MILHOLE 2863.71,693.7 r90 top
TP5 "TESTPOINT" TP_50MIL-25MILHOLE 2955.01,695 r90 top
TP6 "TESTPOINT" TP_50MIL-25MILHOLE 2780.01,695 r90 top
TP7 "TESTPOINT" TP_50MIL-25MILHOLE 1150.01,1675 r0 top
TP8 "TESTPOINT" TP_50MIL-25MILHOLE 2890.01,1405 r90 top
TP9 "TESTPOINT" TP_50MIL-25MILHOLE 2300.01,1420 r90 top
TP10 "TESTPOINT" TP_50MIL-25MILHOLE 1150.01,1600 r90 top
U1 "TMS320F28388DZWTS" ZWT0337A 1861.42,1056.1 r0 top locked
U1:A "TPS73033DBVR" DBV0005A_N 697.16,2071.61 r90 top
U2 "SN74LVC2G07DBVR" DBV0006A_N 1895.01,1630 r270 bottom
U2:A "FT2232HL-REEL" LQFP64_N 518.18,1572.63 r270 bottom
U3 "TPS3702CX33DDCT" DDC0006A_N 2105.01,1905 r0 top
U3:A "TPD2E001DRLR" DRL0005A 477.16,2066.61 r180 bottom
U4 "TPS3702CX12DDCT" DDC0006A_N 2345.01,1905 r0 top
U4:A "93LC56C-I/SN" SOIC-8 517.16,1591.61 r0 top
U5 "CDCLVC1104PW" PW0008A_N 3435.01,470 r180 bottom
U5:A "ISO7220CD" D0008B_N 1068.18,2172.63 r0 top
U6 "REF5030IDGKT" DGK0008A_N 1336.42,556.1 r0 top
U6:A "ISO7220CD" D0008B_N 1070.01,1950 r0 top
U7 "TPD4E001QDBVRQ1" DBV0006A_N 181.02,717.87 r90 top
U7:A "SN74ALVC244PWR" PW0020A_N 1430.01,2000 r0 top
U8 "TPD4E001QDBVRQ1" DBV0006A_N 491.42,717.87 r90 top
U8:A "ISO7220CD" D0008B_N 1066.84,1802.37 r180 bottom
U9 "TPD4E001QDBVRQ1" DBV0006A_N 336.42,717.87 r90 top
U9:A "ISO7220CD" D0008B_N 1060.01,1385.32 r0 top
U10 "TPD4E001QDBVRQ1" DBV0006A_N 646.42,717.87 r90 top
U11 "TPD4E001QDBVRQ1" DBV0006A_N 956.42,717.87 r90 top
U12 "TPD4E001QDBVRQ1" DBV0006A_N 801.42,717.87 r90 top
U13 "OPA4350EA/250" DBQ0016A_N 1361.42,756.1 r0 top
U14 "TPS62420DRCR" DRC0010J 3610.82,937.77 r180 bottom
U15 "TPS2051BDBVR" DBV0005A_N 1673.97,1950 r270 bottom
U16 "TPD4S012DRYR" DRY0006A 1809.69,2086.81 r270 top
U17 "DP83822IRHBR" RHB0032B#1 2691.07,1626.06 r270 bottom
U18 "CAT24C16WI-GT3" SOIC-8 2365.01,1675 r180 top
U19 "DP83822IRHBR" RHB0032B#2 2690.01,2005 r90 top
U20 "SN74LVC2G06DBVR" DBV0006A_N 3645.01,1465 r180 top
U21 "DP83822IRHBR" RHB0032B#2 2686.07,1081.06 r90 top
Y1 "ECS-2520S33-250-FN-TR" ECS_ECS-2520S 3660.01,540 r180 bottom
Y1:A "ECS-120-20-30B-TR" ECS_ECX-53B 132.16,1811.61 r180 bottom
Y2 "ECS-2520S33-200-FN-TR" ECS_ECS-2520S 3850.01,545 r180 bottom
ZZ1 "This Assembly Note is for PCB labels only" AssemblyNoteLabel -2880.86,2910.71 r0 top
ZZ2 "These assemblies are ESD sensitive, ESD precautions shall be observed." AssemblyNote -2880.86,2801.83 r0 top
ZZ3 "These assemblies must be clean and free from flux and all contaminants. Use of no clean flux is not acceptable." AssemblyNote -2880.86,2713.27 r0 top
ZZ4 "These assemblies must comply with workmanship standards IPC-A-610 Class 2, unless otherwise specified." AssemblyNote -2880.86,2624.71 r0 top

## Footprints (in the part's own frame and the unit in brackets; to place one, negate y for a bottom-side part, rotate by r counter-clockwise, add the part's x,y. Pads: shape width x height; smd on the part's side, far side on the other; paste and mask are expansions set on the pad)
3M_2908-05WB-MG [mm] "Connector, Micro SD, R/A, SMD"
  rect 0.8x1.5 smd: 1(0,0) 2(1.1,-0.4) 3(2.2,0) 4(3.3,0.2) 5(4.4,0) 6(5.5,0.2) 7(6.6,0) 8(7.7,0)
  rect 1.4x1.9 smd: S1(-4.66,3.85) S2(8.49,2.85)
  rect 1.8x1.4 smd: S3(6.89,-10.3) S4(1.19,-10.3)
  silkscreen extent -5.06,-10.7 8.94,4.45, body extent -5.06,-10.75 8.94,4.5, height 1.91
0201 [mm] "Data from Kemet datasheet CC101_COM dated 7/28/11"
  rect 0.46x0.42 smd mask+0.048: 1(-0.33,0) 2(0.33,0)
  body extent -0.31,-0.16 0.31,0.16, height 0.26
0402 [mm] "0402 from SM-752 data"
  rect 0.8x0.6 smd: 1(-0.6,0) 2(0.6,0)
  silkscreen extent -1.22,-0.52 1.22,0.52, body extent -0.55,-0.3 0.55,0.3, height 0.6
0402L [mm] "0402 from SM-752 data"
  rect 0.6x0.5 smd: 1(-0.5,0) 2(0.5,0)
  body extent -0.55,-0.3 0.55,0.3, height 0.6
0603 [mm] "0603 from SM-752 data"
  rect 1x0.95 smd: 1(-0.8,0) 2(0.8,0)
  silkscreen extent -1.52,-0.69 1.52,0.69, body extent -0.87,-0.47 0.87,0.47, height 1
0805_HV [mil] "0805 with 30mil clearance between pads"
  rect 50x63 smd: 1(-40,0) 2(40,0)
  silkscreen extent -74,-40 74,40, body extent -43,-29 43,29, height 57
1206 [mm] "1206 from SM-752 data"
  rect 1.3x1.85 smd: 1(-1.45,0) 2(1.45,0)
  silkscreen extent -2.4,-1.21 2.4,1.21, body extent -1.7,-0.9 1.7,0.9, height 1.35
1812_180 [mm] "SMT, 2-Leads, Body 4.5x3.2mm"
  rect 1.85x4.36 smd: 1(-2.53,0) 2(2.53,0)
  silkscreen extent -3.75,-2.48 3.75,2.48, body extent -2.43,-1.75 2.42,1.75, height 1.8
3216-18 [mm] "Based on AVX recommendation in http://www.avx.com/download/software/literature/AVX-Footprint-Library.pdf"
  rrect7% 1.4x1.8 smd: 1(-1.3,0) 2(1.3,0)
  silkscreen extent -1.9,-1.12 0.8,1.12, body extent -1.7,-0.9 1.7,0.9, height 1.82
AssemblyNote [mil] "Assembly Note"
AssemblyNoteLabel [mil] "Assembly Note for PCB Labels"
CE_Mark_5mm [mil] "Minimum text height for CE Mark"
  silkscreen extent -138,-98 138,98
controlCARD-120HSEC_Edge [mm] "Edge Connector, 0.8mm, 60x2, pad numbers do not match Samtec datasheet"
  rect 0.55x2.8 smd paste-2.5 mask+0: 1(-23.6,2.4) 3(-22.8,2.4) 5(-22,2.4) 7(-21.2,2.4) 9(-20.4,2.4) 11(-19.6,2.4) 13(-18.8,2.4) 15(-18,2.4) 17(-17.2,2.4) 19(-16.4,2.4) 21(-15.6,2.4) 23(-14.8,2.4) 25(-14,2.4) 27(-13.2,2.4) 29(-12.4,2.4) 31(-11.6,2.4) 33(-10.8,2.4) 35(-10,2.4) 37(-9.2,2.4) 39(-8.4,2.4) 41(-7.6,2.4) 43(-6.8,2.4) 45(-6,2.4) 47(-5.2,2.4) 49(-4.4,2.4) 51(-3.6,2.4) 53(-2.8,2.4) 55(-2,2.4) 57(2,2.4) 59(2.8,2.4) 61(3.6,2.4) 63(4.4,2.4) 65(5.2,2.4) 67(6,2.4) 69(6.8,2.4) 71(7.6,2.4) 73(8.4,2.4) 75(9.2,2.4) 77(10,2.4) 79(10.8,2.4) 81(11.6,2.4) 83(12.4,2.4) 85(13.2,2.4) 87(14,2.4) 89(14.8,2.4) 91(15.6,2.4) 93(16.4,2.4) 95(17.2,2.4) 97(18,2.4) 99(18.8,2.4) 101(19.6,2.4) 103(20.4,2.4) 105(21.2,2.4) 107(22,2.4) 109(22.8,2.4) 111(23.6,2.4) 113(24.4,2.4) 115(25.2,2.4) 117(26,2.4) 119(26.8,2.4)
  rect 0.55x2.8 smd far side paste-2.5 mask+0: 2(-23.6,2.4) 4(-22.8,2.4) 6(-22,2.4) 8(-21.2,2.4) 10(-20.4,2.4) 12(-19.6,2.4) 14(-18.8,2.4) 16(-18,2.4) 18(-17.2,2.4) 20(-16.4,2.4) 22(-15.6,2.4) 24(-14.8,2.4) 26(-14,2.4) 28(-13.2,2.4) 30(-12.4,2.4) 32(-11.6,2.4) 34(-10.8,2.4) 36(-10,2.4) 38(-9.2,2.4) 40(-8.4,2.4) 42(-7.6,2.4) 44(-6.8,2.4) 46(-6,2.4) 48(-5.2,2.4) 50(-4.4,2.4) 52(-3.6,2.4) 54(-2.8,2.4) 56(-2,2.4) 58(2,2.4) 60(2.8,2.4) 62(3.6,2.4) 64(4.4,2.4) 66(5.2,2.4) 68(6,2.4) 70(6.8,2.4) 72(7.6,2.4) 74(8.4,2.4) 76(9.2,2.4) 78(10,2.4) 80(10.8,2.4) 82(11.6,2.4) 84(12.4,2.4) 86(13.2,2.4) 88(14,2.4) 90(14.8,2.4) 92(15.6,2.4) 94(16.4,2.4) 96(17.2,2.4) 98(18,2.4) 100(18.8,2.4) 102(19.6,2.4) 104(20.4,2.4) 106(21.2,2.4) 108(22,2.4) 110(22.8,2.4) 112(23.6,2.4) 114(24.4,2.4) 116(25.2,2.4) 118(26,2.4) 120(26.8,2.4)
controlCARD-180HSEC-60pinAddon_Edge [mm] "Edge Connector, 0.8mm, 30x2, pad numbers do not match Samtec datasheet"
  rect 0.55x2.8 smd paste-2.5 mask+0: 121(-11.6,2.4) 123(-10.8,2.4) 125(-10,2.4) 127(-9.2,2.4) 129(-8.4,2.4) 131(-7.6,2.4) 133(-6.8,2.4) 135(-6,2.4) 137(-5.2,2.4) 139(-4.4,2.4) 141(-3.6,2.4) 143(-2.8,2.4) 145(-2,2.4) 147(-1.2,2.4) 149(-0.4,2.4) 151(0.4,2.4) 153(1.2,2.4) 155(2,2.4) 157(2.8,2.4) 159(3.6,2.4) 161(4.4,2.4) 163(5.2,2.4) 165(6,2.4) 167(6.8,2.4) 169(7.6,2.4) 171(8.4,2.4) 173(9.2,2.4) 175(10,2.4) 177(10.8,2.4) 179(11.6,2.4)
  rect 0.55x2.8 smd far side paste-2.5 mask+0: 122(-11.6,2.4) 124(-10.8,2.4) 126(-10,2.4) 128(-9.2,2.4) 130(-8.4,2.4) 132(-7.6,2.4) 134(-6.8,2.4) 136(-6,2.4) 138(-5.2,2.4) 140(-4.4,2.4) 142(-3.6,2.4) 144(-2.8,2.4) 146(-2,2.4) 148(-1.2,2.4) 150(-0.4,2.4) 152(0.4,2.4) 154(1.2,2.4) 156(2,2.4) 158(2.8,2.4) 160(3.6,2.4) 162(4.4,2.4) 164(5.2,2.4) 166(6,2.4) 168(6.8,2.4) 170(7.6,2.4) 172(8.4,2.4) 174(9.2,2.4) 176(10,2.4) 178(10.8,2.4) 180(11.6,2.4)
CPF0402 [mm] "TE Connectivity"
  rect 0.5x0.6 smd: 1(-0.5,0) 2(0.5,0)
  silkscreen extent -0.97,-0.53 0.97,0.53, body extent -0.55,-0.27 0.55,0.27, height 0.35
D0008B_N [mil] "SOIC, 8-Leads, Body 4.9x3.9mm, Pitch 1.27mm, IPC Medium Density"
  oval 55x23.62 smd: 1(-108.5,75) 2(-108.5,25) 3(-108.5,-25) 4(-108.5,-75) 5(108.5,-75) 6(108.5,-25) 7(108.5,25) 8(108.5,75)
  silkscreen extent -130,-98 35,98, body extent -118,-96 118,96, height 64
DBQ0016A_N [mm] "SOP, 16-Leads, Body 4.9x3.9mm, Pitch 0.635mm, IPC Medium Density"
  oval 1.45x0.4 smd: 1(-2.725,2.222) 2(-2.725,1.587) 3(-2.725,0.953) 4(-2.725,0.318) 5(-2.725,-0.318) 6(-2.725,-0.953) 7(-2.725,-1.587) 8(-2.725,-2.222) 9(2.725,-2.222) 10(2.725,-1.587) 11(2.725,-0.953) 12(2.725,-0.318) 13(2.725,0.318) 14(2.725,0.953) 15(2.725,1.587) 16(2.725,2.222)
  silkscreen extent -3.35,-2.5 1.1,2.68, body extent -3.01,-2.45 3.01,2.45, height 1.63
